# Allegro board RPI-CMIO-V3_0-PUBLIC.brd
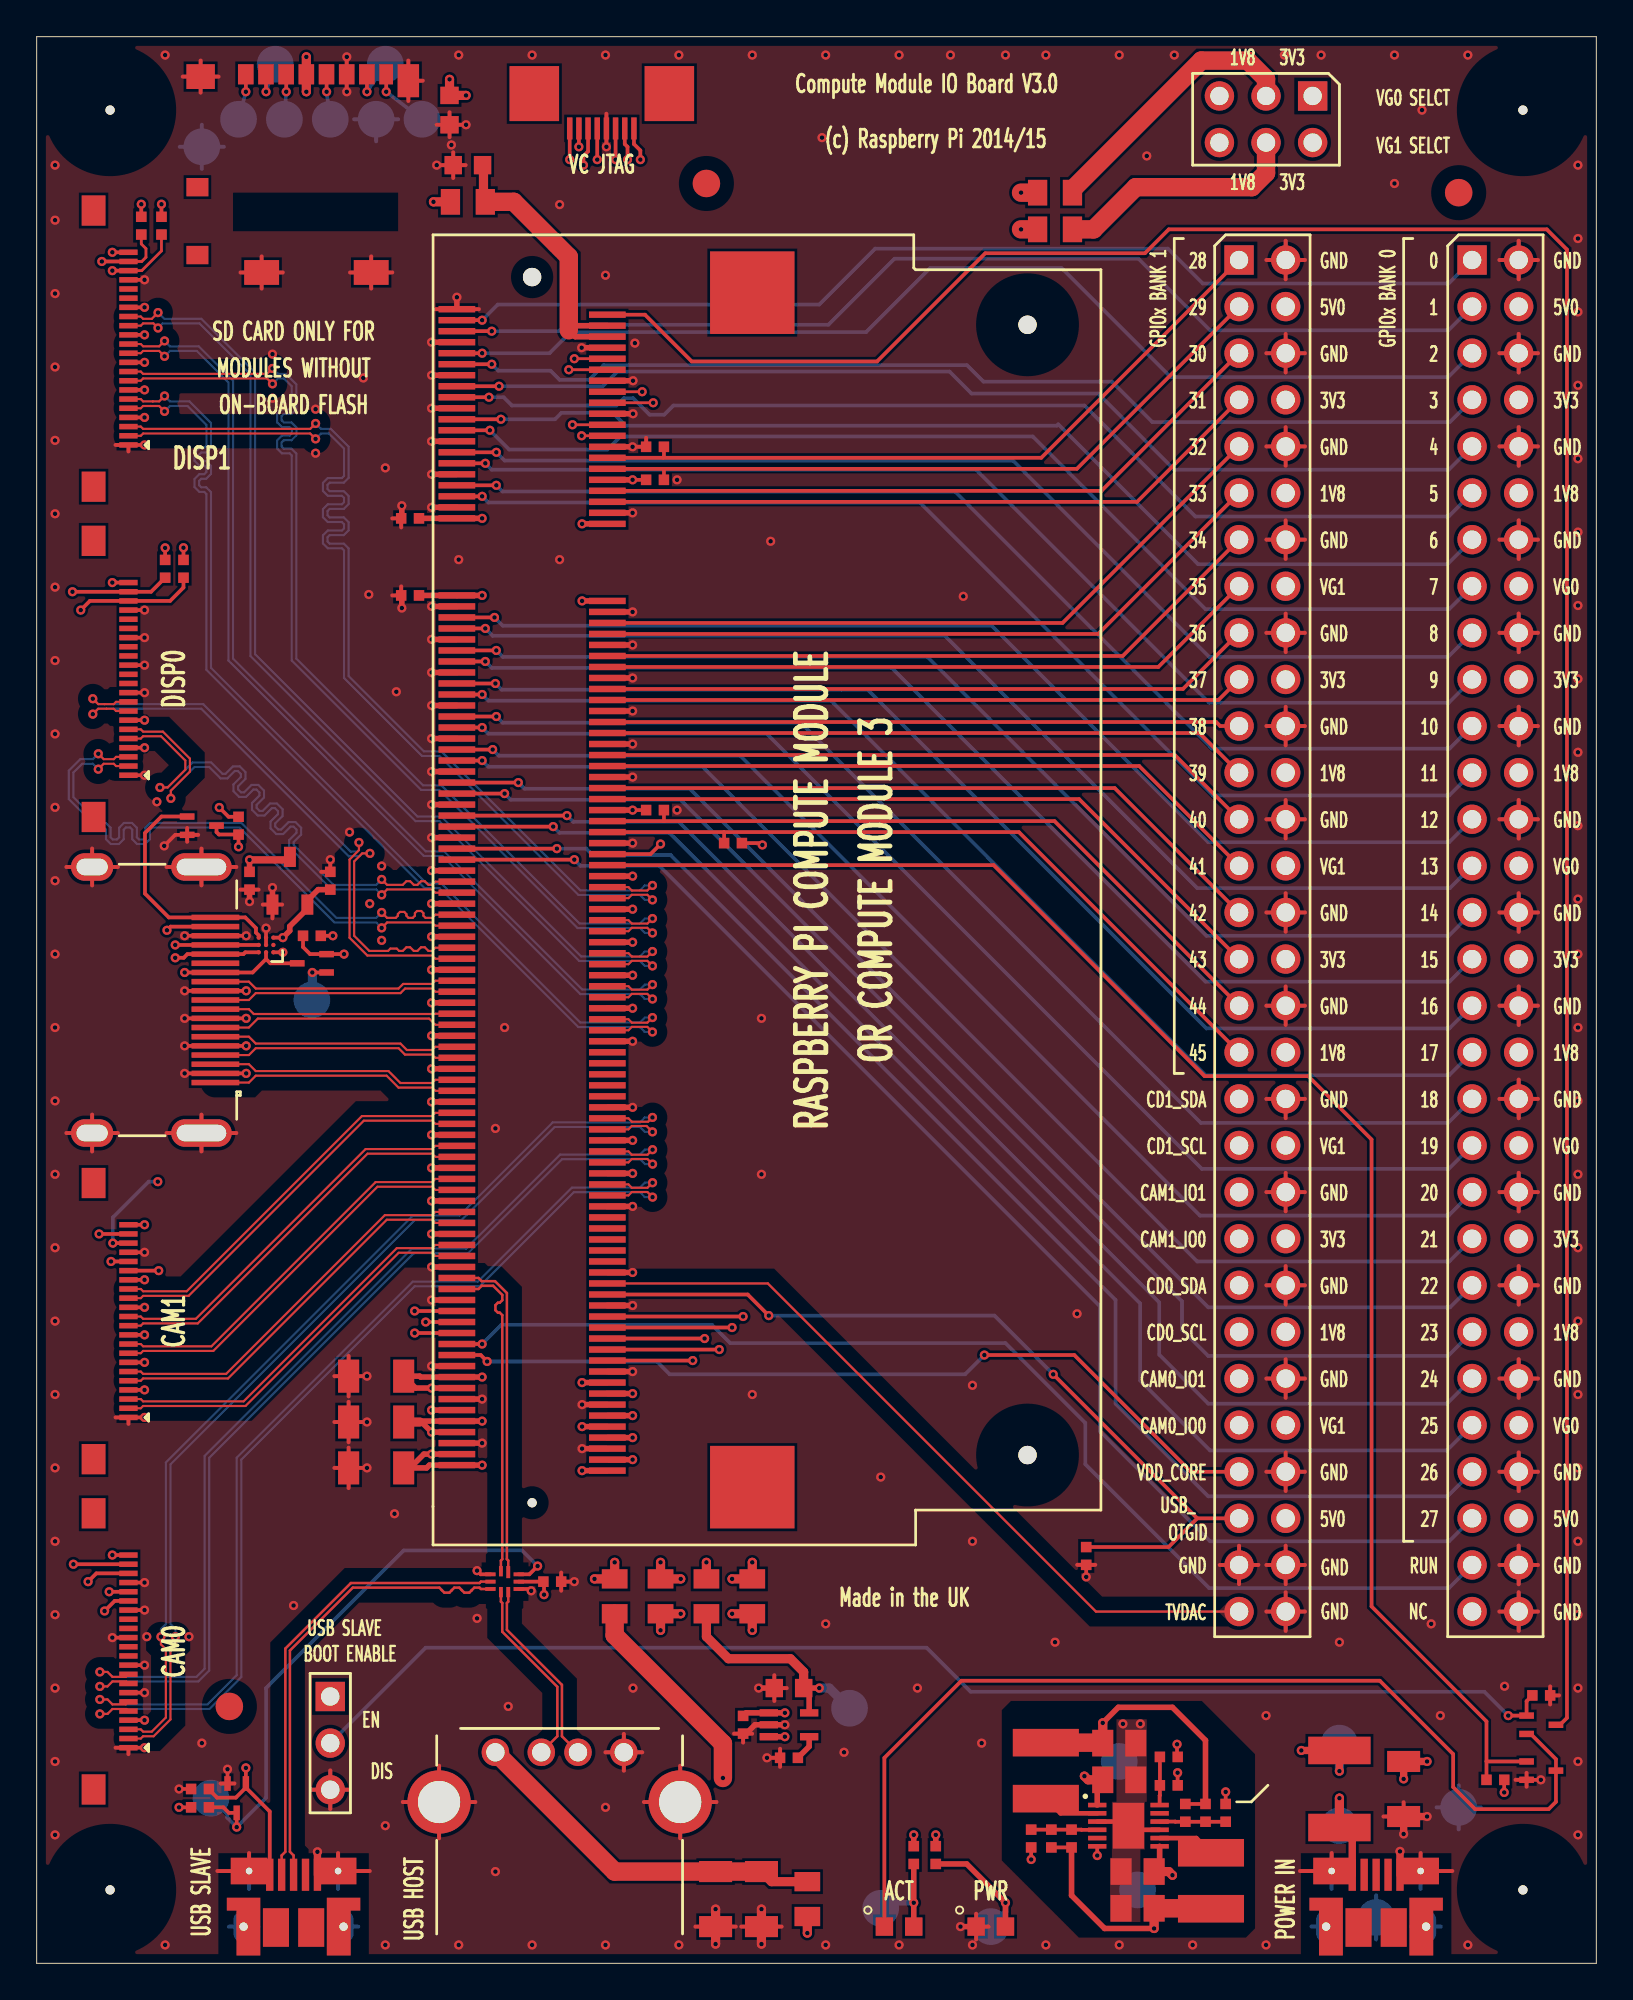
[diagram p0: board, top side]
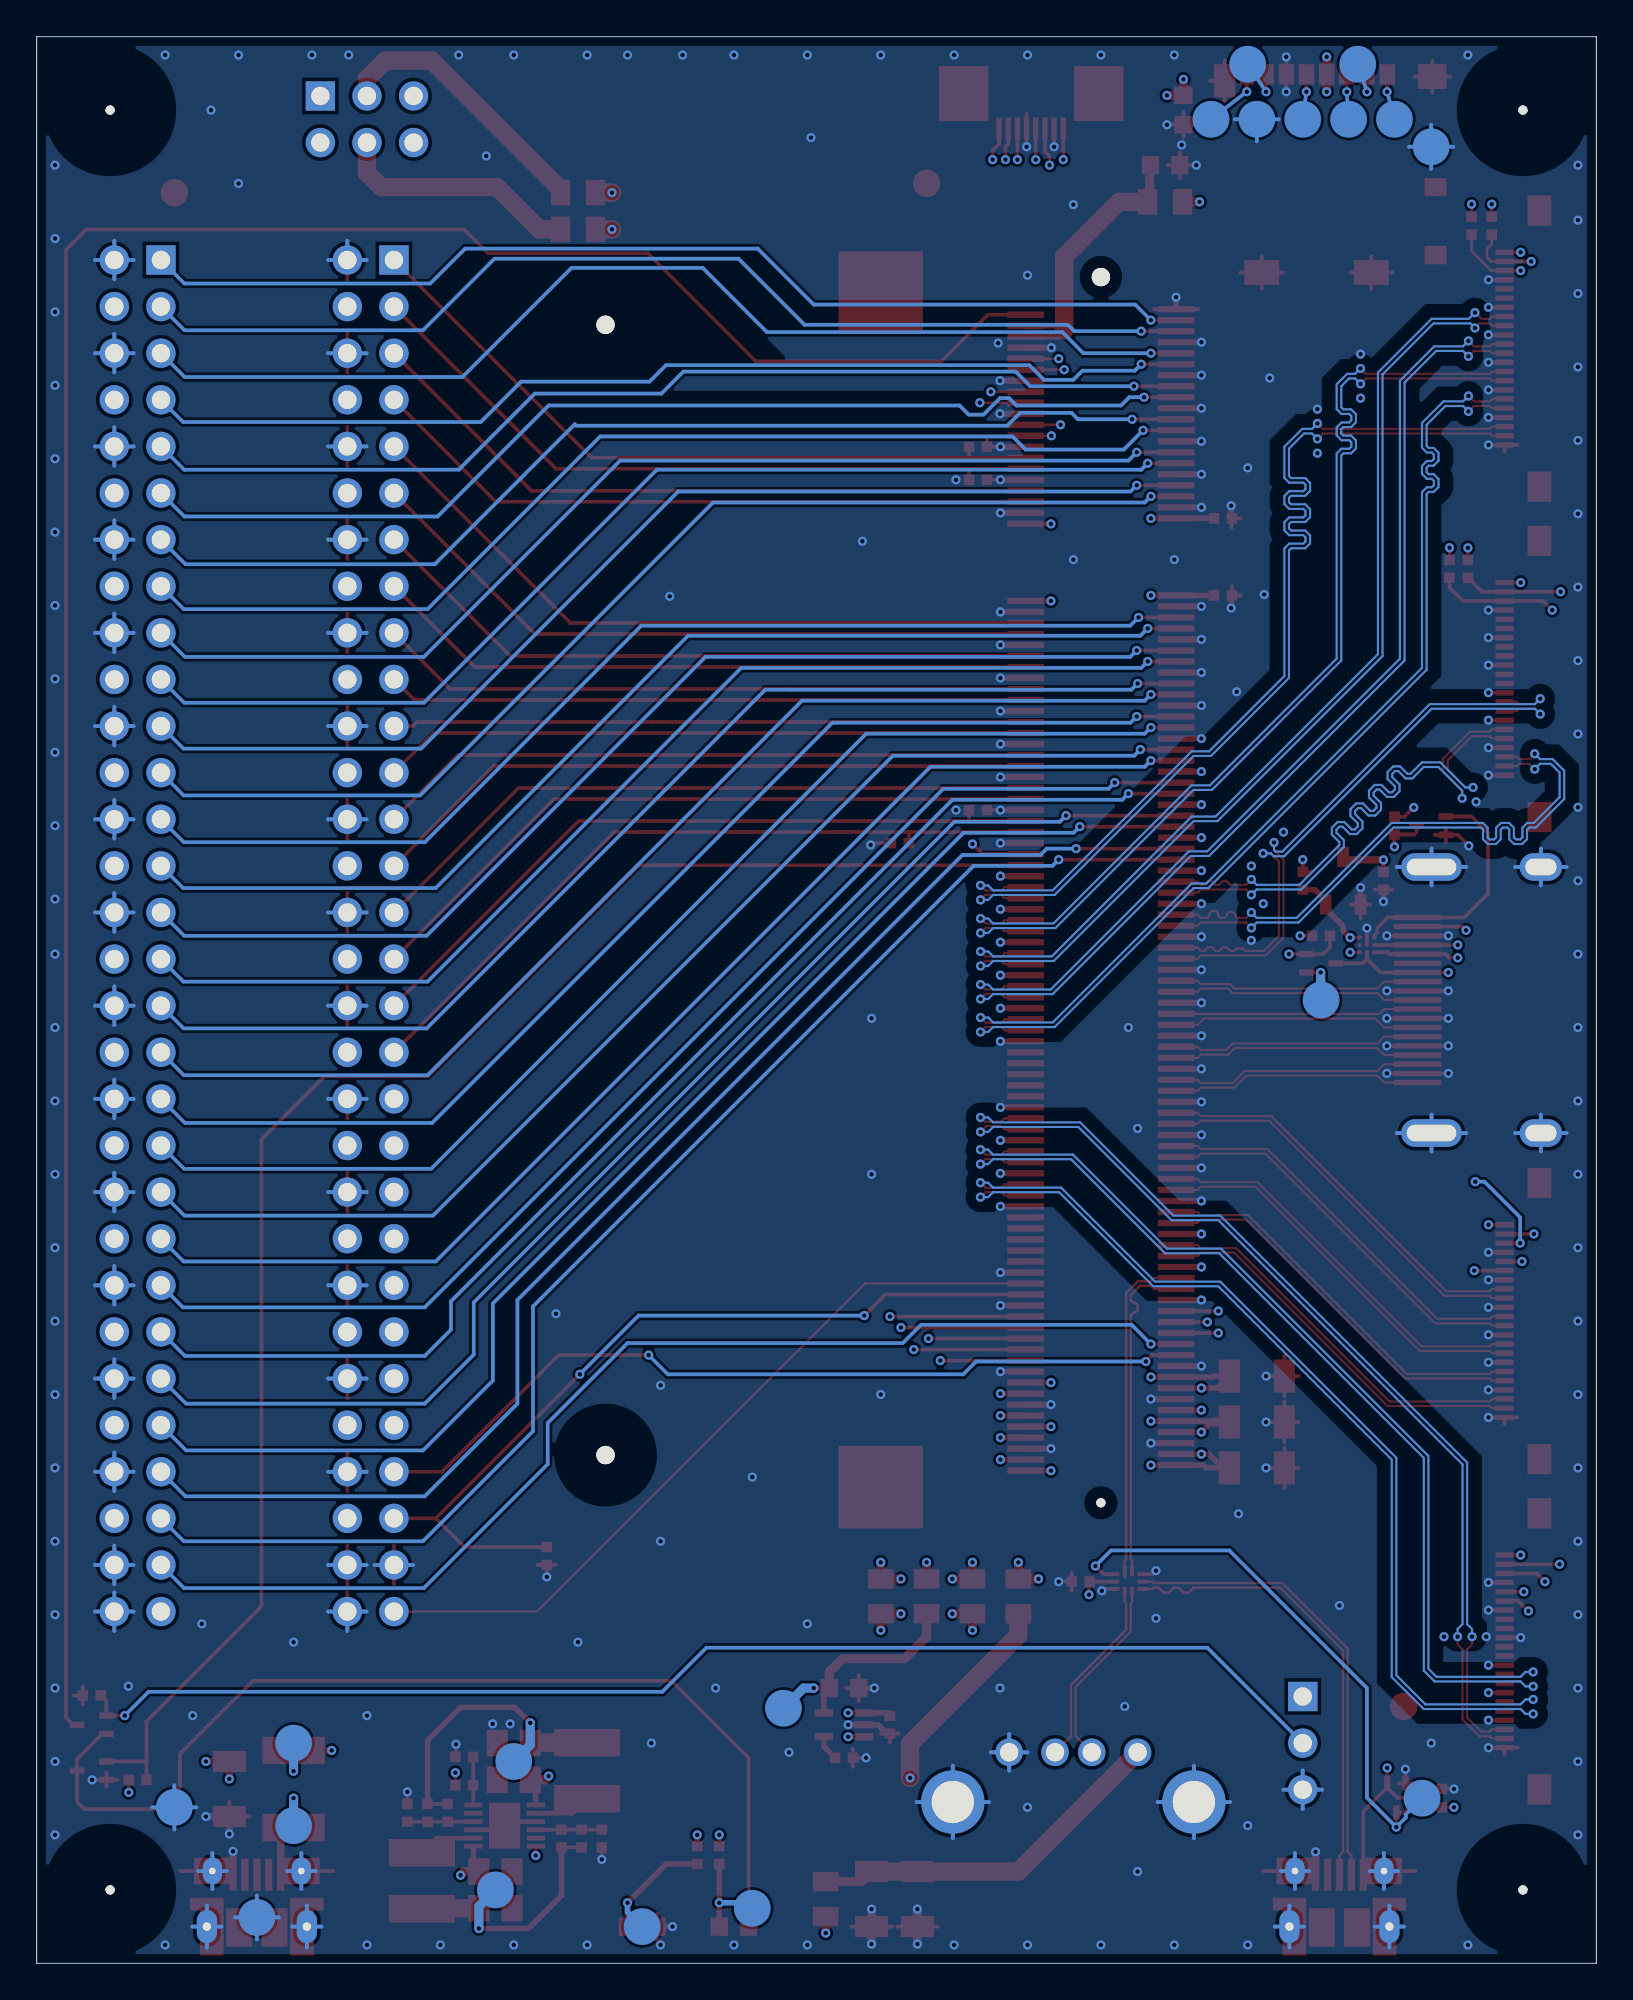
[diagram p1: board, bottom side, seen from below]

Outline 85 x 105 mm; copper layers: TOP, GNDT, PWRT, PWRB, GNDB, BOTTOM. Coordinates in mm from the lower left corner of the outline.
Outline path: 0,105 85,105 85,0 0,0 0,105

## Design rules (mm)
constraint set DEFAULT: min track width 0.115
net group CAM0_CLK: nets CAM0_CN CAM0_CP
net group CAM0_D0: nets CAM0_DN0 CAM0_DP0
net group CAM0_D1: nets CAM0_DN1 CAM0_DP1
net group CAM1_CLK: nets CAM1_CN CAM1_CP
net group CAM1_D0: nets CAM1_DN0 CAM1_DP0
net group CAM1_D1: nets CAM1_DN1 CAM1_DP1
net group CAM1_D2: nets CAM1_DN2 CAM1_DP2
net group CAM1_D3: nets CAM1_DN3 CAM1_DP3
net group DSI0_CLK: nets DSI0_CN DSI0_CP
net group DSI0_D0: nets DSI0_DN0 DSI0_DP0
net group DSI0_D1: nets DSI0_DN1 DSI0_DP1
net group DSI1_CLK: nets DSI1_CN DSI1_CP
net group DSI1_D0: nets DSI1_DN0 DSI1_DP0
net group DSI1_D1: nets DSI1_DN1 DSI1_DP1
net group DSI1_D2: nets DSI1_DN2 DSI1_DP2
net group DSI1_D3: nets DSI1_DN3 DSI1_DP3
net group HDMI_CK: nets HDMI_CK_N HDMI_CK_P
net group HDMI_D0: nets HDMI_D0_N HDMI_D0_P
net group HDMI_D1: nets HDMI_D1_N HDMI_D1_P
net group HDMI_D2: nets HDMI_D2_N HDMI_D2_P
net group USB_D: nets USB_DM USB_DP
net group USBA_D: nets USBA_DM USBA_DP
net group USBB_D: nets USBB_DM USBB_DP

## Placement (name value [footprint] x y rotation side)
C1  47u  [CAPC3216X180N]  18.5 27 180 top
C2  47u  [CAPC3216X180N]  74.5 9.5 270 top
C3  47u  [CAPC3216X180N]  18.5 29.5 180 top
C4  1u  [CAPC1005X55N]  38.5 13 270 top
C5  4.7u  [CAPC1608X90N]  41 15 180 top
C6  100n  [CAPC1005X55N]  61.7 11.25 0 top
C7  10u  [CAPC2012X145N]  60 5 180 top
C8  10u  [CAPC2012X145N]  59 10 0 top
C9  100n  [CAPC1005X55N]  41 11.2 180 top
C10  47u  [CAPC3216X180N]  18.5 32 180 top
C11  10u  [CAPC2012X145N]  60 3 180 top
C12  10u  [CAPC2012X145N]  59 12 0 top
C13  1u  [CAPC1005X55N]  20.35 78.75 180 top
C14  1u  [CAPC1005X55N]  20.35 74.55 180 top
C15  100n  [CAPC1005X55N]  11.6 59 270 top
C16  100n  [CAPC1005X55N]  16 59 90 top
C17  100n  [CAPC1005X55N]  28.1 20.8 180 top
C19  47u  [CAPC3216X180N]  37 3.5 270 top
C20  47u  [CAPC3216X180N]  39.5 3.5 270 top
C21  NF  [CAPC1005X55N]  55.3 6.8 90 top
C22  NF  [CAPC1005X55N]  63.7 8.2 270 top
C23  4.7u  [CAPC1608X90N]  23.5 98 180 top
C24  4.7u  [CAPC1608X90N]  22.5 101 270 top
D1  RED  [LEDC1608X80N]  52 2 0 top
D2  GREEN  [LEDC1608X80N]  47 2 0 top
F1  MF-MSMF200  [BOURNS_MF-MSMF150]  71 9.5 90 top
J1  DDR2 SODIMM  [FCI_10033853_CM]  27 58.5 90 top
J2  10103594-0001LF  [FCI_10103594-0001LF]  73 2 0 top
J3  6W 0.1" PIN HDR  [PINHDR_6W_2P54MM]  67 100.5 180 top
J4  3W 0.1" PIN HDR  [PINHDR_3W_2P54MM]  16 12 270 top
J5  60W 0.1" PIN HDR  [PINHDR_60W_2P54MM]  79.5 56 270 top
J6  60W 0.1" PIN HDR  [PINHDR_60W_2P54MM]  66.8 56 270 top
J7  68710814522  [WE_68710814522]  30.8 100 180 top
J9  54548-2271  [MOLEX_54548-2271]  5 17 270 top
J10  54548-2271  [MOLEX_54548-2271]  5 70 270 top
J11  54548-2271  [MOLEX_54548-2271]  5 35 270 top
J12  54548-2271  [MOLEX_54548-2271]  5 88 270 top
J13  47151-1051  [MOLEX_47151-1051]  6 52.5 270 top
J14  61400416021  [WURTH_61400416021]  28.5 11.5 90 top
J15  10103594-0001LF  [FCI_10103594-0001LF]  14 2 0 top
J16  1040310811  [MOLEX_1040310811]  14.5 98 180 top
L1  4.7u  [BOURNS_SRN4018]  64 4.5 270 top
L2  4.7u  [BOURNS_SRN4018]  55 10.5 90 top
NOREF  -  []  0 105 0 top
NOREF#2  -  []  110 65 0 top
NOREF#3  -  []  85 0 90 top
NOREF#4  -  [unnamed#2]  77.5 96.5 0 top
NOREF#5  -  [unnamed#2]  10.5 14 0 top
NOREF#6  -  []  110 0 0 top
NOREF#7  -  []  110 34 0 top
NOREF#8  -  [unnamed#2]  4 4 0 top
NOREF#9  -  [unnamed#2]  4 101 0 top
NOREF#10  -  [unnamed#2]  81 101 0 top
NOREF#11  -  [unnamed#2]  81 4 0 top
NOREF#12  -  []  0 129 0 top
NOREF#13  -  []  0 166 0 top
NOREF#14  -  [unnamed#2]  36.5 97 0 top
PP1  PP_SMT_ROUND_2MM  [PP_SMT_R2MM]  71 7.5 180 bottom
PP2  PP_SMT_ROUND_2MM  [PP_SMT_R2MM]  60 4 180 bottom
PP3  PP_SMT_ROUND_2MM  [PP_SMT_R2MM]  71 12 180 bottom
PP4  PP_SMT_ROUND_2MM  [PP_SMT_R2MM]  44.3 13.9 180 bottom
PP5  PP_SMT_ROUND_2MM  [PP_SMT_R2MM]  77.5 8.5 180 bottom
PP6  PP_SMT_ROUND_2MM  [PP_SMT_R2MM]  59 11 180 bottom
PP7  PP_SMT_ROUND_2MM  [PP_SMT_R2MM]  52 2 180 bottom
PP8  PP_SMT_ROUND_2MM  [PP_SMT_R2MM]  73 2.5 180 bottom
PP9  PP_SMT_ROUND_2MM  [PP_SMT_R2MM]  46 3 180 bottom
PP10  PP_SMT_ROUND_2MM  [PP_SMT_R2MM]  15 52.5 180 bottom
PP11  PP_SMT_ROUND_2MM  [PP_SMT_R2MM]  9.5 9 180 bottom
PP12  PP_SMT_ROUND_2MM  [PP_SMT_R2MM]  11 100.5 180 bottom
PP13  PP_SMT_ROUND_2MM  [PP_SMT_R2MM]  13 103.5 180 bottom
PP14  PP_SMT_ROUND_2MM  [PP_SMT_R2MM]  13.5 100.5 180 bottom
PP15  PP_SMT_ROUND_2MM  [PP_SMT_R2MM]  16 100.5 180 bottom
PP16  PP_SMT_ROUND_2MM  [PP_SMT_R2MM]  19 103.5 180 bottom
PP17  PP_SMT_ROUND_2MM  [PP_SMT_R2MM]  21 100.5 180 bottom
PP18  PP_SMT_ROUND_2MM  [PP_SMT_R2MM]  18.5 100.5 180 bottom
PP19  PP_SMT_ROUND_2MM  [PP_SMT_R2MM]  9 99 180 bottom
Q1  DMG1012T  [SOT50P160X90-3N]  82 13 0 top
Q2  DMG1012T  [SOT50P160X90-3N]  82 10.5 0 top
Q3  DMG1012T  [SOT50P160X90-3N]  15 54.5 180 top
Q4  DMG1012T  [SOT50P160X90-3N]  9 62 0 top
Q5  DMG1012T  [SOT50P160X90-3N]  10.9 9 270 top
R1  0R  [RESC2012X65N]  31.5 20 90 top
R2  100K  [RESC1005X40N]  61.7 9.7 180 top
R3  470R  [RESC1005X40N]  49 5.9 270 top
R4  0R  [RESC2012X65N]  34 20 90 top
R5  0R  [RESC2012X65N]  39 20 90 top
R6  0R  [RESC2012X65N]  36.5 20 90 top
R7  0R  [RESC2012X65N]  55.5 96.5 0 top
R8  0R  [RESC2012X65N]  55.5 94.5 0 top
R9  470R  [RESC1005X40N]  47.8 5.9 270 top
R10  100K  [RESC1005X40N]  79.5 10 180 top
R12  1K  [RESC1005X40N]  57.2 22.2 90 top
R13  1.8K  [RESC1005X40N]  8 76 270 top
R14  1.8K  [RESC1005X40N]  7 76 270 top
R15  NF  [RESC1005X40N]  15 56 0 top
R16  1.8K  [RESC1005X40N]  6.8 94.7 270 top
R17  1.8K  [RESC1005X40N]  5.7 94.7 270 top
R18  100K  [RESC1005X40N]  11 62 270 top
R19  0R  [RESC2012X65N]  42 3.5 90 top
R20  47K  [RESC1005X40N]  8.9 8.5 0 top
R21  47K  [RESC1005X40N]  8.9 9.5 180 top
R22  0R  [RESC1005X40N]  56.4 6.8 90 top
R23  0R  [RESC1005X40N]  62.6 8.2 270 top
R24  NF  [RESC1005X40N]  64.8 8.2 90 top
R25  NF  [RESC1005X40N]  54.2 6.8 270 top
R26  100K  [RESC1005X40N]  33.7 80.85 180 top
R27  100K  [RESC1005X40N]  33.7 82.65 180 top
R28  100K  [RESC1005X40N]  37.95 61.05 0 top
R29  100K  [RESC1005X40N]  33.7 62.85 180 top
R30  47K  [RESC1005X40N]  82 14.6 0 top
R31  0R  [RESC2012X65N]  23.5 96 180 top
U1  PAM2306AYPKE  [DIODES_PAM2306]  59.5 7.5 0 top
U2  AP7115-25SEG  [SOT65P210X100-5N]  41 13 0 top
U3  AP2331W  [SOT95P280X135-3N]  13.8 59 90 top
U4  ESD5384  [ONSEMI_ESD5384]  12.5 55.5 180 top
U5  FSUSB42UMX  [FAIRCHILD_FSUSB42UMX]  25.5 20.8 270 top

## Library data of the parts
C1-C3 C10 C19 C20 = CAP_3216_6.3V_47u
C4 C13 C14 = CAP_1005_6.3V_1u
C5 C23 C24 = CAP_1608_6.3V_4.7u
C6 C9 C15-C17 = CAP_1005_6.3V_100n
C7 C8 C11 C12 = CAP_2012_6.3V_10u
C21 C22 = CAP_1005_NF
D1 = LED_1608_RED
D2 = LED_1608_GREEN
F1 = FUSE_POLY_2.0A_6V
J1 = CON_200W_DDR2SODIMM_CM
J2 J15 = CON_uUSB_B
J3 = CON_6W_PINHDR
J4 = CON_3W_PINHDR
J5 J6 = CON_60W_PINHDR
J7 = CON_FFC_8W
J9-J12 = CON_22W_FFC_54548-2271
J13 = CON_HDMI_RA
J14 = CON_USBA_RA_PTH
J16 = CON_uSD_1040310811
L1 L2 = IND_4u7_SRN4018-4R7M
PP1-PP19 = PP_SMT_ROUND_2MM
Q1-Q5 = MOSFET_N_DMG1012T
R1 R4-R8 R19 R31 = RES_2012_0R
R2 R10 R18 R26-R29 = RES_1005_100K
R3 R9 = RES_1005_470R
R12 = RES_1005_1K
R13 R14 R16 R17 = RES_1005_1.8K
R15 = RES_1005_27K
R20 R21 R30 = RES_1005_47K
R22 R23 = RES_1005_0R
R24 R25 = RES_1005_NF
U1 = IC_SMPS_DUAL_1A_3V3_1V8
U2 = IC_AP7115-25SEG
U3 = IC_AP2331W
U4 = IC_ESD5384
U5 = IC_MUX2-1_USB

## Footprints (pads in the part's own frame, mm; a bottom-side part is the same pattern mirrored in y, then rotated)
BOURNS_MF-MSMF150
  rect 1.5x3.4 smd: 1(-2.1,0) 2(2.1,0)
BOURNS_SRN4018
  rect 1.5x3.6 smd: 1(-1.525,0) 2(1.525,0)
CAPC1005X55N
  rect 0.57x0.58 smd: 1(-0.485,0) 2(0.485,0)
CAPC1608X90N
  rect 0.95x1 smd: 1(-0.8,0) 2(0.8,0)
CAPC2012X145N
  rect 1.15x1.45 smd: 1(-0.9,0) 2(0.9,0)
CAPC3216X180N
  rect 1.15x1.8 smd: 1(-1.5,0) 2(1.5,0)
DIODES_PAM2306
  rect 1x0.25 smd: 1(-1.7,1.125) 2(-1.7,0.675) 3(-1.7,0.225) 4(-1.7,-0.225) 5(-1.7,-0.675) 6(-1.7,-1.125) 7(1.7,-1.125) 8(1.7,-0.675) 9(1.7,-0.225) 10(1.7,0.225) 11(1.7,0.675) 12(1.7,1.125)
  rect 1.7x2.5 smd: 13(0,0)
FAIRCHILD_FSUSB42UMX
  rect 0.66x0.21 smd: 1(-0.52,0.2)
  rect 0.56x0.21 smd: 2(-0.57,-0.2) 6(0.57,-0.2) 7(0.57,0.2)
  rect 0.21x0.56 smd: 3(-0.4,-0.77) 4(0,-0.77) 5(0.4,-0.77) 8(0.4,0.77) 9(0,0.77) 10(-0.4,0.77)
FCI_10033853_CM
  round 0.5 hole 1.1 unplated: (-33.4,0)
  rect 4.5x4.6 smd: (-32.55,-12) (32.55,-12)
  round 1 hole 2.4 unplated: (-30.8,-27) (30.8,-27)
  round 1 hole 1.6 unplated: (33.4,0)
  rect 0.35x2 smd: 1(31.65,4.1) 2(31.35,-4.1) 3(31.05,4.1) 4(30.75,-4.1) 5(30.45,4.1) 6(30.15,-4.1) 7(29.85,4.1) 8(29.55,-4.1) 9(29.25,4.1) 10(28.95,-4.1) 11(28.65,4.1) 12(28.35,-4.1) 13(28.05,4.1) 14(27.75,-4.1) 15(27.45,4.1) 16(27.15,-4.1) 17(26.85,4.1) 18(26.55,-4.1) 19(26.25,4.1) 20(25.95,-4.1) 21(25.65,4.1) 22(25.35,-4.1) 23(25.05,4.1) 24(24.75,-4.1) 25(24.45,4.1) 26(24.15,-4.1) 27(23.85,4.1) 28(23.55,-4.1) 29(23.25,4.1) 30(22.95,-4.1) 31(22.65,4.1) 32(22.35,-4.1) 33(22.05,4.1) 34(21.75,-4.1) 35(21.45,4.1) 36(21.15,-4.1) 37(20.85,4.1) 38(20.55,-4.1) 39(20.25,4.1) 40(19.95,-4.1) 41(16.05,4.1) 42(15.75,-4.1) 43(15.45,4.1) 44(15.15,-4.1) 45(14.85,4.1) 46(14.55,-4.1) 47(14.25,4.1) 48(13.95,-4.1) 49(13.65,4.1) 50(13.35,-4.1) 51(13.05,4.1) 52(12.75,-4.1) 53(12.45,4.1) 54(12.15,-4.1) 55(11.85,4.1) 56(11.55,-4.1) 57(11.25,4.1) 58(10.95,-4.1) 59(10.65,4.1) 60(10.35,-4.1) 61(10.05,4.1) 62(9.75,-4.1) 63(9.45,4.1) 64(9.15,-4.1) 65(8.85,4.1) 66(8.55,-4.1) 67(8.25,4.1) 68(7.95,-4.1) 69(7.65,4.1) 70(7.35,-4.1) 71(7.05,4.1) 72(6.75,-4.1) 73(6.45,4.1) 74(6.15,-4.1) 75(5.85,4.1) 76(5.55,-4.1) 77(5.25,4.1) 78(4.95,-4.1) 79(4.65,4.1) 80(4.35,-4.1) 81(4.05,4.1) 82(3.75,-4.1) 83(3.45,4.1) 84(3.15,-4.1) 85(2.85,4.1) 86(2.55,-4.1) 87(2.25,4.1) 88(1.95,-4.1) 89(1.65,4.1) 90(1.35,-4.1) 91(1.05,4.1) 92(0.75,-4.1) 93(0.45,4.1) 94(0.15,-4.1) 95(-0.15,4.1) 96(-0.45,-4.1) 97(-0.75,4.1) 98(-1.05,-4.1) 99(-1.35,4.1) 100(-1.65,-4.1) 101(-1.95,4.1) 102(-2.25,-4.1) 103(-2.55,4.1) 104(-2.85,-4.1) 105(-3.15,4.1) 106(-3.45,-4.1) 107(-3.75,4.1) 108(-4.05,-4.1) 109(-4.35,4.1) 110(-4.65,-4.1) 111(-4.95,4.1) 112(-5.25,-4.1) 113(-5.55,4.1) 114(-5.85,-4.1) 115(-6.15,4.1) 116(-6.45,-4.1) 117(-6.75,4.1) 118(-7.05,-4.1) 119(-7.35,4.1) 120(-7.65,-4.1) 121(-7.95,4.1) 122(-8.25,-4.1) 123(-8.55,4.1) 124(-8.85,-4.1) 125(-9.15,4.1) 126(-9.45,-4.1) 127(-9.75,4.1) 128(-10.05,-4.1) 129(-10.35,4.1) 130(-10.65,-4.1) 131(-10.95,4.1) 132(-11.25,-4.1) 133(-11.55,4.1) 134(-11.85,-4.1) 135(-12.15,4.1) 136(-12.45,-4.1) 137(-12.75,4.1) 138(-13.05,-4.1) 139(-13.35,4.1) 140(-13.65,-4.1) 141(-13.95,4.1) 142(-14.25,-4.1) 143(-14.55,4.1) 144(-14.85,-4.1) 145(-15.15,4.1) 146(-15.45,-4.1) 147(-15.75,4.1) 148(-16.05,-4.1) 149(-16.35,4.1) 150(-16.65,-4.1) 151(-16.95,4.1) 152(-17.25,-4.1) 153(-17.55,4.1) 154(-17.85,-4.1) 155(-18.15,4.1) 156(-18.45,-4.1) 157(-18.75,4.1) 158(-19.05,-4.1) 159(-19.35,4.1) 160(-19.65,-4.1) 161(-19.95,4.1) 162(-20.25,-4.1) 163(-20.55,4.1) 164(-20.85,-4.1) 165(-21.15,4.1) 166(-21.45,-4.1) 167(-21.75,4.1) 168(-22.05,-4.1) 169(-22.35,4.1) 170(-22.65,-4.1) 171(-22.95,4.1) 172(-23.25,-4.1) 173(-23.55,4.1) 174(-23.85,-4.1) 175(-24.15,4.1) 176(-24.45,-4.1) 177(-24.75,4.1) 178(-25.05,-4.1) 179(-25.35,4.1) 180(-25.65,-4.1) 181(-25.95,4.1) 182(-26.25,-4.1) 183(-26.55,4.1) 184(-26.85,-4.1) 185(-27.15,4.1) 186(-27.45,-4.1) 187(-27.75,4.1) 188(-28.05,-4.1) 189(-28.35,4.1) 190(-28.65,-4.1) 191(-28.95,4.1) 192(-29.25,-4.1) 193(-29.55,4.1) 194(-29.85,-4.1) 195(-30.15,4.1) 196(-30.45,-4.1) 197(-30.75,4.1) 198(-31.05,-4.1) 199(-31.35,4.1) 200(-31.65,-4.1)
FCI_10103594-0001LF
  rect 1.42x2.1 smd: (-0.96,-0.05) (0.96,-0.05)
  rect 0.4x1.75 smd: 1(-1.3,2.825) 2(-0.65,2.825) 3(0,2.825) 4(0.65,2.825) 5(1.3,2.825)
  custom 0.362x0.362 hole 1.05x0.65: 6(-2.425,3.03) 8(2.425,3.03)
  custom 0.456x0.456 hole 0.7x1.4: 7(-2.725,0) 9(2.725,0)
LEDC1608X80N
  rect 0.95x1 smd: 1(-0.8,0) 2(0.8,0)
MOLEX_47151-1051
  rect 0.3x2.6 smd: 1(4.5,3.74) 2(4,3.74) 3(3.5,3.74) 4(3,3.74) 5(2.5,3.74) 6(2,3.74) 7(1.5,3.74) 8(1,3.74) 9(0.5,3.74) 10(0,3.74) 11(-0.5,3.74) 12(-1,3.74) 13(-1.5,3.74) 14(-2,3.74) 15(-2.5,3.74) 16(-3,3.74) 17(-3.5,3.74) 18(-4,3.74) 19(-4.5,3.74)
  oval 1.5x3.3 hole 0.9x2.7: 20(7.25,2.98) 22(-7.25,2.98)
  oval 1.5x2.3 hole 0.9x1.7: 21(7.25,-2.98) 23(-7.25,-2.98)
MOLEX_54548-2271
  rect 1.65x1.3 smd: (-7.525,-1.9) (7.525,-1.9)
  rect 0.3x1 smd: 1(5.25,0) 2(4.75,0) 3(4.25,0) 4(3.75,0) 5(3.25,0) 6(2.75,0) 7(2.25,0) 8(1.75,0) 9(1.25,0) 10(0.75,0) 11(0.25,0) 12(-0.25,0) 13(-0.75,0) 14(-1.25,0) 15(-1.75,0) 16(-2.25,0) 17(-2.75,0) 18(-3.25,0) 19(-3.75,0) 20(-4.25,0) 21(-4.75,0) 22(-5.25,0)
MOLEX_1040310811
  rect 0.85x1.1 smd: 1(3.105,-4.95) 2(2.005,-4.95) 3(0.905,-4.95) 4(-0.195,-4.95) 5(-1.295,-4.95) 6(-2.395,-4.95) 7(-3.495,-4.95)
  rect 0.75x1.1 smd: 8(-4.545,-4.95)
  rect 1.2x1 smd: 9(5.74,1.2) 10(5.74,4.9)
  rect 1.17x1.8 smd: 11(-5.755,-4.6)
  rect 1.55x1.35 smd: 12(5.565,-4.825)
  rect 1.9x1.35 smd: 13(2.24,5.85) 14(-3.73,5.85)
ONSEMI_ESD5384
  round 0.235 smd: A1(-0.4,0.4) A2(0,0.4) A3(0.4,0.4) B1(-0.4,0) B2(0,0) B3(0.4,0) C1(-0.4,-0.4) C2(0,-0.4) C3(0.4,-0.4)
PINHDR_3W_2P54MM
  rect 1.6x1.6 hole 1: 1(-2.54,0)
  round 1.6 hole 1: 2(0,0) 3(2.54,0)
PINHDR_6W_2P54MM
  rect 1.6x1.6 hole 1: 1(-2.54,-1.27)
  round 1.6 hole 1: 2(-2.54,1.27) 3(0,-1.27) 4(0,1.27) 5(2.54,-1.27) 6(2.54,1.27)
PINHDR_60W_2P54MM
  rect 1.6x1.6 hole 1: 1(-36.83,-1.27)
  round 1.6 hole 1: 2(-36.83,1.27) 3(-34.29,-1.27) 4(-34.29,1.27) 5(-31.75,-1.27) 6(-31.75,1.27) 7(-29.21,-1.27) 8(-29.21,1.27) 9(-26.67,-1.27) 10(-26.67,1.27) 11(-24.13,-1.27) 12(-24.13,1.27) 13(-21.59,-1.27) 14(-21.59,1.27) 15(-19.05,-1.27) 16(-19.05,1.27) 17(-16.51,-1.27) 18(-16.51,1.27) 19(-13.97,-1.27) 20(-13.97,1.27) 21(-11.43,-1.27) 22(-11.43,1.27) 23(-8.89,-1.27) 24(-8.89,1.27) 25(-6.35,-1.27) 26(-6.35,1.27) 27(-3.81,-1.27) 28(-3.81,1.27) 29(-1.27,-1.27) 30(-1.27,1.27) 31(1.27,-1.27) 32(1.27,1.27) 33(3.81,-1.27) 34(3.81,1.27) 35(6.35,-1.27) 36(6.35,1.27) 37(8.89,-1.27) 38(8.89,1.27) 39(11.43,-1.27) 40(11.43,1.27) 41(13.97,-1.27) 42(13.97,1.27) 43(16.51,-1.27) 44(16.51,1.27) 45(19.05,-1.27) 46(19.05,1.27) 47(21.59,-1.27) 48(21.59,1.27) 49(24.13,-1.27) 50(24.13,1.27) 51(26.67,-1.27) 52(26.67,1.27) 53(29.21,-1.27) 54(29.21,1.27) 55(31.75,-1.27) 56(31.75,1.27) 57(34.29,-1.27) 58(34.29,1.27) 59(36.83,-1.27) 60(36.83,1.27)
PP_SMT_R2MM
  round 2 smd: 1(0,0)
RESC1005X40N
  rect 0.57x0.58 smd: 1(-0.485,0) 2(0.485,0)
RESC2012X65N
  rect 1.05x1.4 smd: 1(-0.95,0) 2(0.95,0)
SOT50P160X90-3N
  rect 0.8x0.35 smd: 1(-0.8,0.5) 2(-0.8,-0.5) 3(0.8,0)
SOT65P210X100-5N
  rect 1x0.4 smd: 1(-1.1,0.65) 2(-1.1,0) 3(-1.1,-0.65) 4(1.1,-0.65) 5(1.1,0.65)
SOT95P280X135-3N
  rect 1.1x0.65 smd: 1(-1.3,0.95) 2(-1.3,-0.95) 3(1.3,0)
unnamed#2
  round 1.5 smd: (0,0)
WE_68710814522
  rect 2.7x3 smd: (-3.68,-1.9) (3.68,-1.9)
  rect 0.3x1.2 smd: 1(-1.75,0) 2(-1.25,0) 3(-0.75,0) 4(-0.25,0) 5(0.25,0) 6(0.75,0) 7(1.25,0) 8(1.75,0)
WURTH_61400416021
  round 1.5 hole 1: 1(0,3.5) 2(0,1) 3(0,-1) 4(0,-3.5)
  round 3.45 hole 2.3: 5(-2.71,6.57) 6(-2.71,-6.57)

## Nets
1V8: C12.1 C22.1 J3.5 J3.6(P6) J5.12 J5.24 J5.36 J5.48 J6.12 J6.24 J6.36 J6.48 L2.2 PP6.1 R5.1 R10.1 R18.1 R23.1
3V3: C4.1 C11.1 C17.2 C21.1 C24.1 J3.1 J3.2 J5.8 J5.20 J5.32 J5.44 J6.8 J6.20 J6.32 J6.44 J9.22 J10.22 J11.22 J12.22 J16.4 L1.2 PP2.1 R3.1 R4.1 R9.1 R13.1 R14.1 R15.2 R16.1 R17.1 R20.1 R22.1 R31.2 U2.1 U2.3 U5.9(VCC)
5V: C2.1 C7.1 C8.1 C15.1 F1.2(P2) J5.4 J5.56 J6.4 J6.56 PP3.1 R1.1 R2.1 R19.1 U1.1(VIN2) U1.6 U1.7 U3.3
GND: C1.2 C2.2 C3.2 C4.2 C5.2 C6.2 C7.2 C8.2 C9.2 C10.2 C11.2 C12.2 C13.2 C14.2 C15.2 C16.2 C17.1 C19.2 C20.2 C23.2 C24.2 D1.1(CATHODE) J1.1 J1.7 J1.8 J1.13 J1.14 J1.19 J1.20 J1.25 J1.26 J1.31 J1.32 J1.37 J1.38 J1.43 J1.44 J1.49 J1.50 J1.55 J1.56 J1.61 J1.62 J1.67 J1.68 J1.73 J1.74 J1.79 J1.80 J1.85 J1.86 J1.91 J1.92 J1.97 J1.98 J1.103 J1.104 J1.109 J1.110 J1.115 J1.116 J1.121 J1.122 J1.127 J1.133 J1.134 J1.139 J1.140 J1.145 J1.146 J1.151 J1.152 J1.157 J1.163 J1.164 J1.169 J1.170 J1.181 J1.182 J1.187 J1.188 J1.195 J1.196 J2.5 J2.6 J2.7 J2.8 J2.9(SH4) J4.3(P3) J5.2 J5.6 J5.10 J5.14 J5.18 J5.22 J5.26 J5.30 J5.34 J5.38 J5.42 J5.46 J5.50 J5.54 J5.58 J5.60 J6.2 J6.6 J6.10 J6.14 J6.18 J6.22 J6.26 J6.30 J6.34 J6.38 J6.42 J6.46 J6.50 J6.54 J6.57 J6.58 J6.60 J7.4 J7.7 J9.1 J9.4 J9.7 J9.10 J9.13 J9.16 J9.19 J10.1 J10.4 J10.7 J10.10 J10.13 J10.16 J10.19 J11.1 J11.4 J11.7 J11.10 J11.13 J11.16 J11.19 J12.1 J12.4 J12.7 J12.10 J12.13 J12.16 J12.19 J13.2 J13.5 J13.8 J13.11 J13.17 J13.20 J13.21 J13.22 J13.23(SH4) J14.4 J14.5 J14.6(P6) J15.5 J15.6 J15.7 J15.8 J15.9(SH4) J16.6(VSS) J16.11 J16.12 J16.13 J16.14 PP5.1 PP8.1 PP18.1 PP19.1 Q2.2(S) Q4.2(S) Q5.2(S) R12.1 R21.2 R24.2 R25.2 R26.2 R27.2 R28.2 R29.2 R30.2 U1.3 U1.9 U1.13 U2.2 U3.1 U4.B2 U4.C2 U5.3 U5.8
VBUSA: C19.1 C20.1 J14.1 R19.2
VBUSB: J4.1 J15.1 Q5.1 R21.1
VDD_CORE: J1.179 J6.53
CAM0_CN: J1.144 J9.8
CAM0_CP: J1.142 J9.9(P9)
CAM0_DN0: J1.138 J9.2
CAM0_DN1: J1.150 J9.5
CAM0_DP0: J1.136 J9.3
CAM0_DP1: J1.148 J9.6
CAM0_IO0: J6.51 J9.17
CAM0_IO1: J6.49 J9.18
CAM1_CN: J1.149 J11.8
CAM1_CP: J1.147 J11.9(P9)
CAM1_DN0: J1.161 J11.2
CAM1_DN1: J1.155 J11.5
CAM1_DN2: J1.143 J11.11
CAM1_DN3: J1.137 J11.14
CAM1_DP0: J1.159 J11.3
CAM1_DP1: J1.153 J11.6
CAM1_DP2: J1.141 J11.12
CAM1_DP3: J1.135 J11.15
CAM1_IO0: J6.43 J11.17
CAM1_IO1: J6.41 J11.18
CD0_SCL: J6.47 J9.20 J10.20 R13.2
CD0_SDA: J6.45 J9.21 J10.21 R14.2
CD1_SCL: J6.39 J11.20 J12.20 R16.2
CD1_SDA: J6.37 J11.21 J12.21 R17.2
CEC: J13.13 Q3.3 U4.A2
CM_1V8: C10.1 J1.183 J1.184 J1.185 J1.186 R5.2
CM_3V3: C3.1 J1.191 J1.192 J1.193 J1.194 R4.2
CM_VBAT: C1.1 J1.197 J1.198 J1.199 J1.200 R1.2
CM_VDAC: J1.189 J1.190 R6.2
DAC_2V5: C5.1 PP4.1 R6.1 U2.5(VOUT)
DSI0_CN: J1.105 J10.8
DSI0_CP: J1.107 J10.9(P9)
DSI0_DN0: J1.99 J10.2
DSI0_DN1: J1.93 J10.5
DSI0_DP0: J1.101 J10.3
DSI0_DP1: J1.95 J10.6
DSI1_CN: J1.102 J12.8
DSI1_CP: J1.100 J12.9(P9)
DSI1_DN0: J1.96 J12.2
DSI1_DN1: J1.120 J12.5
DSI1_DN2: J1.114 J12.11
DSI1_DN3: J1.108 J12.14
DSI1_DP0: J1.94 J12.3
DSI1_DP1: J1.118 J12.6
DSI1_DP2: J1.112 J12.12
DSI1_DP3: J1.106 J12.15
EMMC_DISABLE_N: J1.2 Q1.3
EMMC_EN_N_1V8: J1.90 Q2.1 R10.2
GPIO0: J1.3 J5.1
GPIO0-27_VREF: C13.1 J1.39 J1.40 R7.1
GPIO1: J1.5 J5.3
GPIO2: J1.9 J5.5
GPIO3: J1.11 J5.7
GPIO4: J1.15 J5.9(P9)
GPIO5: J1.17 J5.11
GPIO6: J1.21 J5.13
GPIO7: J1.23 J5.15
GPIO8: J1.27 J5.17
GPIO9: J1.29 J5.19
GPIO10: J1.33 J5.21
GPIO11: J1.35 J5.23
GPIO12: J1.45 J5.25
GPIO13: J1.47 J5.27
GPIO14: J1.51 J5.29
GPIO15: J1.53 J5.31
GPIO16: J1.57 J5.33
GPIO17: J1.59 J5.35
GPIO18: J1.63 J5.37
GPIO19: J1.65 J5.39
GPIO20: J1.69 J5.41
GPIO21: J1.71 J5.43
GPIO22: J1.75 J5.45
GPIO23: J1.77 J5.47
GPIO24: J1.81 J5.49
GPIO25: J1.83 J5.51
GPIO26: J1.87 J5.53
GPIO27: J1.89 J5.55
GPIO28: J1.28 J6.1 R27.1
GPIO28-45_VREF: C14.1 J1.41 J1.42 R8.1
GPIO29: J1.30 J6.3 R26.1
GPIO30: J1.34 J6.5
GPIO31: J1.36 J6.7
GPIO32: J1.46 J6.9(P9)
GPIO33: J1.48 J6.11
GPIO34: J1.52 J6.13
GPIO35: J1.54 J6.15
GPIO36: J1.58 J6.17
GPIO37: J1.60 J6.19
GPIO38: J1.64 J6.21
GPIO39: J1.66 J6.23
GPIO40: J1.70 J6.25
GPIO41: J1.72 J6.27
GPIO42: J1.76 J6.29
GPIO43: J1.78 J6.31
GPIO44: J1.82 J6.33 R29.1
GPIO45: J1.84 J6.35 R28.1
H5V: C16.1 J13.18 PP10.1 Q3.1 U3.2(OUT) U4.A1 U4.C1
HDMI_CEC: J1.171 Q3.2(S) R15.1
HDMI_CK_N: J1.111 J13.12
HDMI_CK_P: J1.113 J13.10
HDMI_D0_N: J1.117 J13.9
HDMI_D0_P: J1.119 J13.7
HDMI_D1_N: J1.123 J13.6
HDMI_D1_P: J1.125 J13.4
HDMI_D2_N: J1.129 J13.3
HDMI_D2_P: J1.131 J13.1
HDMI_HPD: J13.19 Q4.1 U4.C3
HDMI_HPD_N_1V8: J1.88 Q4.3 R18.2
HDMI_SCL: J1.175 J13.15 U4.A3
HDMI_SDA: J1.173 J13.16 U4.B3(SDA)
RUN: J1.177 J5.57 J7.1
SDX_CLK: J1.10 J16.5 PP15.1
SDX_CMD: J1.12 J16.3 PP14.1
SDX_D0: J1.16 J16.7 PP16.1
SDX_D1: J1.18 J16.8 PP17.1
SDX_D2: J1.22 J16.1 PP12.1
SDX_D3: J1.24 J16.2 PP13.1
SDX_VREF: C23.1 J1.4 J1.6 R31.1
TVDAC: J1.166 J6.59
USB_DM: J1.167 U5.2
USB_DP: J1.165 U5.1
USB_OTGID: J1.168 J6.55 R12.2
USBA_DM: J14.2 U5.6
USBA_DP: J14.3 U5.7
USBB_DM: J15.2 U5.4
USBB_DP: J15.3 U5.5
VC_TCK: J1.180 J7.8(P8)
VC_TDI: J1.174 J7.3
VC_TDO: J1.178 J7.5
VC_TMS: J1.176 J7.6
VC_TRST_N: J1.172 J7.2
VG0: J3.3 J5.16 J5.28 J5.40 J5.52 R7.2
VG1: J3.4 J6.16 J6.28 J6.40 J6.52 R8.2
N1195355: D2.2 PP9.1 R9.2
N1195439: D2.1(CATHODE) Q1.2(S) Q2.3
N1202496: C6.1 R2.2 U1.12
N1202592: L1.1 U1.8
N1202604: L2.1 U1.2
N1202780: F1.1 J2.1 PP1.1
N1203166: C9.1 U2.4
N1203318: D1.2 PP7.1 R3.2
N1313759: C21.2 R22.2 R25.1 U1.4
N1313939: C22.2 R23.2 R24.1 U1.10
N1329395: PP11.1 Q5.3 R20.2 U5.10
N1357591: J4.2 Q1.1 R30.1

Pads without a net: J1 124 126 128 130 132 154 156 158 160 162; J2 2 3 4; J5 59; J9 11 12 14 15; J10 11 12 14 15 17 18; J12 17 18; J13 14; J15 4; J16 9 10; U1 5 11; U4 B1

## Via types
v1: diameter 0.5, hole 0.25, TOP to BOTTOM, 476 vias

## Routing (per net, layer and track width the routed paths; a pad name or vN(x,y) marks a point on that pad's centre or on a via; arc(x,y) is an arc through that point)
1V8: length 64.9
  TOP w0.2: R18.1 10.46,62.48 v1(9.95,62.99) ; R10.1 79.98,9.99 v1(79.98,9.31) ; 63.67,8.68 63.7,8.65 ; R23.1 C22.1
  TOP w0.3: v1(58.1,13.1) 58.95,13.95 61.9,13.95 63.7,12.15 C22.1 63.7,8.65
  TOP w0.5: v1(39,18.15) R5.1 v1(37.9,19.05) ; C12.1 v1(58.1,13.1)
  TOP w1: C12.1 58.08,12.03 L2.2
  PWRT w0.2: 80,12.45 79.98,12.43 v1(79.98,9.31)
  PWRT w0.215: 79.67,49.65 J5.36 ; J5.36 80.77,48.55 ; J5.36 80.77,50.75 ; 79.67,34.41 J5.48 ; J5.48 80.77,35.51 ; J5.48 80.77,33.31 ; J6.48 68.07,35.51 ; J6.48 69.17,34.41 ; J6.48 68.07,33.31 ; J6.48 66.97,34.41 ; 68.07,63.79 J6.24 ; J6.24 66.97,64.89 ; J6.24 68.07,65.99 ; J6.24 69.17,64.89 ; 63.36,99.23 J3.6 ; J3.6 64.46,98.13 ; J3.6 65.56,99.23 ; J3.6 64.46,100.33 ; 79.67,80.13 J5.12 ; J5.12 80.77,79.03 ; J5.12 80.77,81.23 ; J3.5 64.46,102.87 ; J3.5 65.56,101.77 ; J3.5 63.36,101.77 ; J6.12 68.07,81.23 ; J6.12 68.07,79.03 ; J6.12 69.17,80.13 ; J6.12 66.97,80.13 ; J5.24 80.77,65.99 ; J5.24 79.67,64.89 ; J5.24 80.77,63.79 ; J6.36 69.17,49.65 ; J6.36 66.97,49.65 ; J6.36 68.07,48.55 ; J6.36 68.07,50.75
  PWRT w0.3: 64.5,100.5 64.46,100.54 J3.5
  BOTTOM w0.5: PP6.1 58.1,11.9 v1(58.1,13.1)
3V3: length 79.3
  TOP w0.2: J10.22 v1(4.12,75.25) ; R17.1 v1(5.7,95.87) ; 7,76.48 R14.1 v1(7,77.14) ; 56.37,6.35 56.4,6.32 ; 15.48,56 R15.2 v1(16.14,56) ; v1(27.65,20.09) 27.65,20.8 C17.2 U5.9 ; 55.3,6.32 56.4,6.32 ; J12.22 v1(4.12,93.25) ; J11.22 v1(5.88,40.25) ; J9.22 v1(4.12,22.25) ; v1(7.76,8.5) R20.1 8.42,8.5 ; R16.1 v1(6.8,95.87) ; v1(8,77.15) R13.1 8,76.48
  TOP w0.3: v1(49,7) 49,6.38 ; v1(60.9,1.9) 58.2,1.9 56.4,3.7 56.4,6.32 ; U2.3 v1(40.78,12.35) ; C4.1 38.66,13.65 U2.1 v1(40.78,13.65) ; v1(47.8,7) 47.8,6.38
  TOP w0.5: v1(14.7,103.9) J16.4 v1(14.7,102) ; v1(34,18.15) R4.1 v1(35.1,19.05) ; v1(23.4,101.8) C24.1 v1(22.5,102.67) ; R31.2 v1(21.62,96) ; C11.1 v1(60.9,1.9)
  TOP w1: L1.2 63.98,3 C11.1
  PWRB w0.215: J5.44 80.77,40.59 ; J5.44 80.77,38.39 ; J5.44 81.87,39.49 ; J5.44 79.67,39.49 ; J6.32 68.07,55.83 ; J6.32 66.97,54.73 ; J6.32 69.17,54.73 ; J6.32 68.07,53.63 ; 68.07,68.87 J6.20 ; J6.20 66.97,69.97 ; J6.20 68.07,71.07 ; J6.20 69.17,69.97 ; 79.67,69.97 J5.20 ; J5.20 80.77,68.87 ; J5.20 80.77,71.07 ; J5.20 81.87,69.97 ; J3.2 69.54,100.33 ; J3.2 69.54,98.13 ; J3.2 70.64,99.23 ; J3.2 68.44,99.23 ; J5.32 81.87,54.73 ; J5.32 79.67,54.73 ; J5.32 80.77,55.83 ; J5.32 80.77,53.63 ; 68.07,84.11 J6.8 ; J6.8 66.97,85.21 ; J6.8 69.17,85.21 ; J6.8 68.07,86.31 ; J5.8 81.87,85.21 ; J5.8 79.67,85.21 ; J5.8 80.77,86.31 ; J5.8 80.77,84.11 ; 68.44,101.77 J3.1 ; J3.1 69.54,100.67 ; J3.1 70.64,101.77 ; J6.44 68.07,40.59 ; J6.44 69.17,39.49 ; J6.44 66.97,39.49 ; J6.44 68.07,38.39
  BOTTOM w0.5: PP2.1 60.9,3.1 v1(60.9,1.9)
5V: length 46.2
  TOP w0.2: v1(62.18,10.39) 62.18,9.71 R2.1 ; U1.6 v1(57.8,5.87)
  TOP w0.3: C8.1 57.8,9.7 U1.1 ; U1.7 61.2,5.3 C7.1 ; v1(11.6,60.14) C15.1 11.6,59.45
  TOP w0.4: v1(11.6,60.14) 13.64,60.14 U3.3 ; v1(68.92,11.6) F1.2 v1(71,10.47) ; v1(74.5,10.05) C2.1 v1(75.78,11)
  TOP w0.5: C8.1 57.3,10 v1(57.1,10.2) ; R19.1 v1(42,1.65) ; v1(61.9,4.8) 61.7,5 C7.1
  TOP w1: v1(37.4,10.1) 37.4,11.97 31.5,17.88 R1.1
  PWRT w0.215: 80.77,89.19 J5.4 ; J5.4 81.87,90.29 ; J5.4 79.67,90.29 ; J5.4 80.77,91.39 ; J5.56 81.87,24.25 ; J5.56 79.67,24.25 ; J5.56 80.77,23.15 ; J5.56 80.77,25.35 ; J6.4 68.07,91.39 ; J6.4 68.07,89.19 ; J6.4 69.17,90.29 ; J6.4 66.97,90.29 ; J6.56 69.17,24.25 ; J6.56 66.97,24.25 ; J6.56 68.07,23.15 ; J6.56 68.07,25.35
  BOTTOM w0.5: v1(71,10.47) PP3.1
GND: length 1063.6
  TOP w0.2: J9.10 v1(5.88,16.25) ; v1(57.2,21.06) R12.1 57.2,21.72 ; 54.2,6.32 v1(54.2,5.66) ; J12.4 v1(5.88,84.25) ; J11.7 v1(5.88,32.75) ; J10.10 v1(5.88,69.25) ; 33.22,62.85 R29.2 v1(32.48,62.85) ; v1(11.42,50) J13.5 v1(8.06,50) ; J9.13 v1(4.12,17.75) ; C6.2 62.15,11.29 v1(62.15,11.94) ; U4.B2 U4.C2 v1(12.5,56.42) ; v1(7.76,9.5) R21.2 8.42,9.5 ; J10.16 v1(5.88,72.25) ; Q2.2 v1(81.98,10) ; J10.7 v1(5.88,67.75) ; 33.22,80.85 R26.2 v1(32.48,80.85) ; v1(8.06,48.5) J13.2 v1(11.42,48.5) ; J11.4 v1(5.88,31.25) ; J9.4 v1(5.88,13.25) ; U5.3 24.2,21.2 v1(24,21.4) ; Q5.2 v1(10.4,10.58) ; J12.1 v1(5.88,82.75) ; v1(64.8,9.34) R24.2 64.8,8.68 ; v1(8.06,51.5) J13.8 v1(11.42,51.5) ; v1(39.55,60.95) 39.45,61.05 R28.2 38.43,61.05 ; J10.1 v1(5.88,64.75) ; v1(6.95,60.9) 7.55,61.5 Q4.2 ; v1(11.42,53) J13.11 v1(8.06,53) ; J10.19 v1(5.88,73.75) ; J12.10 v1(5.88,87.25) ; J10.13 v1(5.88,70.75) ; U5.8 26.95,20.4 ; J11.13 v1(5.88,35.75) ; J11.10 v1(5.88,34.25) ; v1(11.42,56) J13.17 v1(8.06,56) ; J12.7 v1(5.88,85.75) ; J9.7 v1(5.88,14.75) ; J9.1 v1(5.88,11.75) ; J12.19 v1(5.88,91.75) ; J12.13 v1(5.88,88.75) ; J11.16 v1(5.88,37.25) ; J9.16 v1(5.88,19.25) ; J10.4 v1(5.88,66.25) ; J12.16 v1(5.88,90.25) ; v1(29.55,99) J7.7 ; J11.1 v1(5.88,29.75) ; J9.19 v1(5.88,20.75) ; J11.19 v1(5.88,38.75)
  TOP w0.215: 79.72,26.79 J5.54 ; J5.54 80.77,27.84 ; J5.54 81.82,26.79 ; J5.54 80.77,25.74 ; Q2.2 81.2,10.38 ; Q2.2 80.6,10 ; Q2.2 81.2,9.62 ; J5.26 80.77,63.4 ; J5.26 79.72,62.35 ; J5.26 80.77,61.3 ; J5.26 81.82,62.35 ; R30.2 82.97,14.6 ; R30.2 82.48,14.11 ; R30.2 82.48,15.09 ; 68.07,40.98 J6.42 ; J6.42 68.07,43.08 ; J6.42 69.12,42.03 ; J6.42 67.02,42.03 ; 7.08,59.75 J13.22 ; J13.22 10.88,59.75 ; J13.22 8.98,60.75 ; J13.22 8.98,58.75 ; 12.09,58.52 C15.2 11.11,58.52 ; 35.9,2 C19.2 38.1,2 ; 22.02,98 C23.2 ; C23.2 22.7,97.3 ; C23.2 23.38,98 ; C23.2 22.7,98.7 ; 16.89,102.2 J16.6 16.89,103.7 ; J6.18 68.07,73.56 ; J6.18 68.07,71.46 ; J6.18 69.12,72.51 ; J6.18 67.02,72.51 ; J5.30 81.82,57.27 ; J5.30 80.77,58.32 ; J5.30 79.72,57.27 ; J5.30 80.77,56.22 ; 38.4,2 C20.2 40.6,2 ; U3.1 13.38,57.7 ; U3.1 12.85,56.95 ; U3.1 12.32,57.7 ; 68.07,66.38 J6.22 ; J6.22 68.07,68.48 ; J6.22 69.12,67.43 ; J6.22 67.02,67.43 ; 32.73,82.65 R27.2 33.22,83.14 ; 79.72,52.19 J5.34 ; J5.34 80.77,53.24 ; J5.34 80.77,51.14 ; J5.34 81.82,52.19 ; 68.07,18.12 J6.60 ; J6.60 69.12,19.17 ; J6.60 67.02,19.17 ; J6.60 68.07,20.22 ; D1.1 51.88,2 ; D1.1 51.2,2.7 ; D1.1 51.2,1.3 ; 19.86,78.75 19.86,79.24 ; 19.86,78.75 19.86,78.26 ; 19.86,78.75 19.38,78.75 ; 67.02,82.67 J6.10 ; J6.10 68.07,83.72 ; J6.10 69.12,82.67 ; J6.10 68.07,81.62 ; 8.94,101.95 8.94,102.83 ; 8.94,102.83 7.96,102.83 ; 8.94,102.83 9.91,102.83 ; 8.94,102.83 8.94,103.7 ; J6.6 68.07,88.8 ; J6.6 67.02,87.75 ; J6.6 68.07,86.7 ; J6.6 69.12,87.75 ; 80.77,40.98 J5.42 ; J5.42 80.77,43.08 ; J5.42 81.82,42.03 ; J5.42 79.72,42.03 ; J5.14 81.82,77.59 ; J5.14 80.77,76.54 ; J5.14 80.77,78.64 ; J5.14 79.72,77.59 ; J5.2 81.82,92.83 ; J5.2 80.77,93.88 ; J5.2 79.72,92.83 ; J5.2 80.77,91.78 ; J13.21 4.42,45.25 ; J13.21 3.02,46.25 ; J13.21 1.62,45.25 ; J13.21 3.02,44.25 ; 15.51,59.48 C16.2 16,59.97 ; C24.2 23.2,100.2 ; C24.2 22.5,99.52 ; C24.2 22.5,100.88 ; C24.2 21.8,100.2 ; 5,29.4 J11.1 4.3,29.75 ; 79.72,21.71 J5.58 ; J5.58 80.77,20.66 ; J5.58 81.82,21.71 ; J5.58 80.77,22.76 ; 19.95,8.79 J14.5 ; J14.5 23.91,8.79 ; J14.5 21.93,6.81 ; J14.5 21.93,10.77 ; C1.2 17,28.1 ; C1.2 17.78,27 ; C1.2 17,25.9 ; C1.2 16.22,27 ; 21.7,90.15 J1.1 24.1,90.15 ; 80.77,86.7 J5.6 ; J5.6 79.72,87.75 ; J5.6 80.77,88.8 ; J5.6 81.82,87.75 ; 16,8.41 J4.3 ; J4.3 16,10.51 ; J4.3 17.05,9.46 ; J4.3 14.95,9.46 ; J6.46 68.07,38 ; J6.46 67.02,36.95 ; J6.46 68.07,35.9 ; J6.46 69.12,36.95 ; J6.58 68.07,22.76 ; J6.58 68.07,20.66 ; J6.58 67.02,21.71 ; J6.58 69.12,21.71 ; J13.20 10.88,45.25 ; J13.20 8.98,44.25 ; J13.20 7.08,45.25 ; J13.20 8.98,46.25 ; 68.07,46.06 J6.38 ; J6.38 69.12,47.11 ; J6.38 67.02,47.11 ; J5.10 81.82,82.67 ; J5.10 79.72,82.67 ; J5.10 80.77,83.72 ; J5.10 80.77,81.62 ; 68.07,56.22 J6.30 ; J6.30 69.12,57.27 ; J6.30 67.02,57.27 ; J6.30 68.07,58.32 ; 80.77,18.12 J5.60 ; J5.60 79.72,19.17 ; J5.60 80.77,20.22 ; J5.60 81.82,19.17 ; J5.46 80.77,38 ; J5.46 80.77,35.9 ; J5.46 79.72,36.95 ; J5.46 81.82,36.95 ; 79.72,47.11 J5.38 ; J5.38 80.77,46.06 ; J5.38 80.77,48.16 ; J5.38 81.82,47.11 ; J13.23 3.02,60.75 ; J13.23 1.62,59.75 ; J13.23 4.42,59.75 ; J13.23 3.02,58.75 ; 8.2,61.12 Q4.2 ; Q4.2 8.8,61.5 ; Q4.2 8.2,61.88 ; 79.72,72.51 J5.18 ; J5.18 80.77,73.56 ; J5.18 81.82,72.51 ; J5.18 80.77,71.46 ; 79.72,67.43 J5.22 ; J5.22 80.77,66.38 ; J5.22 81.82,67.43 ; J5.22 80.77,68.48 ; C17.1 28.59,21.29 ; C17.1 29.07,20.8 ; C17.1 28.59,20.31 ; C3.2 17,30.6 ; C3.2 16.22,29.5 ; C3.2 17.78,29.5 ; C3.2 17,28.4 ; 16.43,6.01 J15.8 18.15,5.03 ; J6.54 68.07,27.84 ; J6.54 69.12,26.79 ; J6.54 68.07,25.74 ; J6.54 67.02,26.79 ; 20.25,101.5 J16.11 ; J16.11 21.04,102.6 ; J16.11 20.25,103.7 ; J6.50 68.07,32.92 ; J6.50 67.02,31.87 ; J6.50 69.12,31.87 ; J6.50 68.07,30.82 ; 77.15,5.03 J2.8 75.42,6.01 ; 65.53,20.66 J6.57 ; J6.57 64.48,21.71 ; J6.57 65.53,22.76 ; J6.57 66.58,21.71 ; J14.4 33,11.5 ; J14.4 31,11.5 ; J14.4 32,12.5 ; J14.4 32,10.5 ; J6.14 69.12,77.59 ; J6.14 67.02,77.59 ; J6.14 68.07,76.54 ; J6.14 68.07,78.64 ; 35.07,6.81 J14.6 ; J14.6 33.09,8.79 ; J14.6 37.05,8.79 ; J14.6 35.07,10.77 ; 9.85,5.03 J15.6 11.57,6.01 ; 79.72,31.87 J5.50 ; J5.50 80.77,32.92 ; J5.50 80.77,30.82 ; J5.50 81.82,31.87 ; 17.08,92.15 J16.14 ; J16.14 18.23,91.27 ; J16.14 18.23,93.03 ; J16.14 19.38,92.15 ; J16.13 13.41,92.15 ; J16.13 12.26,93.03 ; J16.13 12.26,91.27 ; J16.13 11.11,92.15 ; 17,30.9 C10.2 ; C10.2 17,33.1 ; C10.2 16.22,32 ; C10.2 17.78,32 ; 56.71,21.71 R12.1 57.69,21.71 ; 67.02,92.83 J6.2 ; J6.2 68.07,91.78 ; J6.2 69.12,92.83 ; J6.2 68.07,93.88 ; 4.3,82.75 J12.1 5,82.4 ; 68.07,51.14 J6.34 ; J6.34 69.12,52.19 ; J6.34 67.02,52.19 ; J6.34 68.07,53.24 ; C4.2 38.99,12.52 ; C4.2 38.01,12.52 ; C4.2 38.5,12.03 ; 31.05,100.8 J7.4 31.05,99.2 ; 40.2,14.3 C5.2 ; C5.2 40.2,15.7 ; C5.2 40.88,15 ; 19.86,74.55 19.86,75.04 ; 19.86,74.55 19.86,74.06 ; 19.86,74.55 19.38,74.55 ; J6.26 69.12,62.35 ; J6.26 67.02,62.35 ; J6.26 68.07,61.3 ; J6.26 68.07,63.4 ; 73.4,8 C2.2 74.5,8.78 ; C9.2 40.52,11.69 ; C9.2 40.52,10.71 ; C9.2 40.03,11.2 ; 5,11.4 J9.1 4.3,11.75 ; 10.78,9.8 Q5.2 10.02,9.8 ; 68.85,5.03 J2.6 70.58,6.01
  TOP w0.25: U1.9 59.73,7.28 U1.13 59.27,7.72 U1.3
  TOP w0.3: 19.9,74.55 v1(19.9,73.86) ; J1.145 v1(21.52,43.35) ; J1.8 v1(29.7,88.05) 29.65,88.05 ; J1.196 v1(29.72,28.05) ; J1.116 v1(32.48,52.05) ; J1.139 v1(21.52,45.15) ; J1.151 v1(21.52,41.55) ; J1.181 v1(21.52,32.55) ; J1.61 v1(21.52,68.55) ; J1.188 v1(29.72,30.45) ; J1.122 v1(32.48,50.25) ; J1.56 v1(32.48,70.05) ; J1.85 v1(21.52,61.35) ; J1.73 v1(21.52,64.95) ; J1.13 v1(21.52,86.55) ; 11.6,58.55 C15.2 v1(11.6,57.86) ; J1.7 v1(21.52,88.35) ; J1.97 v1(21.52,57.75) ; J1.103 v1(21.52,55.95) ; J1.157 v1(21.52,39.75) ; J1.195 v1(24.28,28.35) ; J1.133 v1(21.52,46.95) ; J1.44 v1(32.48,73.65) ; 38.5,12.55 38.7,12.55 39.15,13 U2.2 v1(40.78,13) ; D1.1 v1(50.35,2) ; J1.146 v1(32.48,43.05) ; J1.163 v1(21.52,37.95) ; U3.1 v1(12.85,58.63) ; J1.115 v1(21.52,52.35) ; J1.152 v1(32.48,41.25) ; J1.109 v1(21.52,54.15) ; J1.91 v1(21.52,59.55) ; J1.98 v1(32.48,57.45) ; J1.169 v1(21.52,36.15) ; J1.62 v1(32.48,68.25) ; 19.9,78.75 v1(19.9,79.44) ; v1(22.9,90.8) J1.1 ; J1.170 v1(32.48,35.85) ; J1.187 v1(24.28,30.75) ; J1.49 v1(21.52,72.15) ; J1.121 v1(21.52,50.55) ; J1.164 v1(32.48,37.65) ; J1.67 v1(21.52,66.75) ; J1.86 v1(32.48,61.05) ; J1.110 v1(32.48,53.85) ; J1.19 v1(21.52,84.75) ; J1.74 v1(32.48,64.65) ; J1.50 v1(32.48,71.85) ; J1.32 v1(32.48,80.85) ; J1.55 v1(21.52,70.35) ; J1.80 v1(32.48,62.85) ; J1.182 v1(32.48,32.25) ; J1.26 v1(32.48,82.65) ; J1.140 v1(32.48,44.85) ; C5.2 v1(39.35,15) ; J1.37 v1(21.52,79.35) ; J1.14 v1(32.5,86.25) ; J1.25 v1(21.52,82.95) ; J1.134 v1(32.48,46.65) ; J1.43 v1(21.52,73.95) ; J1.68 v1(32.48,66.45) ; J1.38 v1(32.48,79.05) ; J1.20 v1(32.5,84.45) ; J1.104 v1(32.48,55.65) ; J1.31 v1(21.52,81.15) ; J1.79 v1(21.52,63.15) ; J1.92 v1(32.48,59.25) ; J1.127 v1(21.52,48.75)
  TOP w0.4: v1(75.78,8) C2.2 v1(74.5,7.05) ; J15.5 v1(15.3,6.08) ; J2.5 v1(74.3,6.1)
  TOP w0.5: v1(37,1.05) C19.2 v1(37,2.95) ; v1(39.5,2.95) C20.2 v1(39.5,1.05)
  GNDT w0.215: J5.60 81.87,19.17 ; J5.60 80.77,20.27 ; J5.60 80.77,18.07 ; J5.60 79.67,19.17 ; J4.3 16,10.56 ; J4.3 16,8.36 ; J4.3 17.1,9.46 ; J4.3 14.9,9.46 ; 35.07,6.76 J14.6 ; J14.6 37.1,8.79 ; J14.6 33.04,8.79 ; J14.6 35.07,10.82 ; 80.77,40.93 J5.42 ; J5.42 79.67,42.03 ; J5.42 81.87,42.03 ; J5.42 80.77,43.13 ; J13.23 3.02,60.8 ; J13.23 1.57,59.75 ; J13.23 3.02,58.7 ; J13.23 4.47,59.75 ; 16.43,4 J15.8 ; J15.8 15.6,5.03 ; J15.8 16.43,6.06 ; J15.8 17.25,5.03 ; 66.97,36.95 J6.46 ; J6.46 69.17,36.95 ; J6.46 68.07,38.05 ; J6.46 68.07,35.85 ; J13.20 8.98,46.3 ; J13.20 8.98,44.2 ; J13.20 10.93,45.25 ; J13.20 7.03,45.25 ; J13.21 3.02,46.3 ; J13.21 1.57,45.25 ; J13.21 3.02,44.2 ; J13.21 4.47,45.25 ; 10.42,2 J15.7 ; J15.7 11.28,3.2 ; J15.7 11.28,0.8 ; J15.7 12.13,2 ; 68.07,91.73 J6.2 ; J6.2 69.17,92.83 ; J6.2 68.07,93.93 ; J6.2 66.97,92.83 ; 68.07,46.01 J6.38 ; J6.38 66.97,47.11 ; J6.38 68.07,48.21 ; J6.38 69.17,47.11 ; J2.7 71.13,2 ; J2.7 69.42,2 ; J2.7 70.28,0.8 ; J2.7 70.28,3.2 ; J5.54 80.77,27.89 ; J5.54 81.87,26.79 ; J5.54 79.67,26.79 ; J5.54 80.77,25.69 ; J2.8 76.25,5.03 ; J2.8 75.42,4 ; J2.8 75.42,6.06 ; J2.8 74.6,5.03 ; J6.50 69.17,31.87 ; J6.50 68.07,30.77 ; J6.50 68.07,32.97 ; J6.50 66.97,31.87 ; J6.22 69.17,67.43 ; J6.22 66.97,67.43 ; J6.22 68.07,66.33 ; J6.22 68.07,68.53 ; J5.34 80.77,53.29 ; J5.34 79.67,52.19 ; J5.34 80.77,51.09 ; J5.34 81.87,52.19 ; 66.97,72.51 J6.18 ; J6.18 68.07,71.41 ; J6.18 68.07,73.61 ; J6.18 69.17,72.51 ; 32,10.45 J14.4 ; J14.4 32,12.55 ; J14.4 30.95,11.5 ; J14.4 33.05,11.5 ; J2.6 70.58,6.06 ; J2.6 69.75,5.03 ; J2.6 71.4,5.03 ; J2.6 70.58,4 ; J6.14 68.07,78.69 ; J6.14 66.97,77.59 ; J6.14 68.07,76.49 ; J6.14 69.17,77.59 ; J6.30 69.17,57.27 ; J6.30 66.97,57.27 ; J6.30 68.07,58.37 ; J6.30 68.07,56.17 ; 80.77,81.57 J5.10 ; J5.10 81.87,82.67 ; J5.10 79.67,82.67 ; J5.10 80.77,83.77 ; J6.60 69.17,19.17 ; J6.60 68.07,18.07 ; J6.60 68.07,20.27 ; J6.60 66.97,19.17 ; 75.72,0.8 J2.9 ; J2.9 75.72,3.2 ; J2.9 76.58,2 ; J2.9 74.87,2 ; J13.22 8.98,60.8 ; J13.22 10.93,59.75 ; J13.22 8.98,58.7 ; J13.22 7.03,59.75 ; 68.07,81.57 J6.10 ; J6.10 66.97,82.67 ; J6.10 69.17,82.67 ; J6.10 68.07,83.77 ; 80.77,76.49 J5.14 ; J5.14 80.77,78.69 ; J5.14 81.87,77.59 ; J5.14 79.67,77.59 ; J5.6 81.87,87.75 ; J5.6 80.77,86.65 ; J5.6 80.77,88.85 ; J5.6 79.67,87.75 ; J15.6 11.57,6.06 ; J15.6 12.4,5.03 ; J15.6 10.75,5.03 ; J15.6 11.57,4 ; J5.18 81.87,72.51 ; J5.18 80.77,73.61 ; J5.18 79.67,72.51 ; J5.18 80.77,71.41 ; 19.9,8.79 J14.5 ; J14.5 21.93,10.82 ; J14.5 23.96,8.79 ; J14.5 21.93,6.76 ; J5.26 81.87,62.35 ; J5.26 79.67,62.35 ; J5.26 80.77,61.25 ; J5.26 80.77,63.45 ; 68.07,51.09 J6.34 ; J6.34 66.97,52.19 ; J6.34 69.17,52.19 ; J6.34 68.07,53.29 ; 66.97,87.75 J6.6 ; J6.6 68.07,88.85 ; J6.6 68.07,86.65 ; J6.6 69.17,87.75 ; J5.30 81.87,57.27 ; J5.30 80.77,58.37 ; J5.30 80.77,56.17 ; J5.30 79.67,57.27 ; 80.77,91.73 J5.2 ; J5.2 79.67,92.83 ; J5.2 80.77,93.93 ; J5.2 81.87,92.83 ; 68.07,20.61 J6.58 ; J6.58 68.07,22.81 ; J6.58 66.97,21.71 ; J6.58 69.17,21.71 ; J6.57 66.63,21.71 ; J6.57 65.53,22.81 ; J6.57 65.53,20.61 ; J6.57 64.43,21.71 ; J5.38 81.87,47.11 ; J5.38 79.67,47.11 ; J5.38 80.77,48.21 ; J5.38 80.77,46.01 ; J5.22 80.77,68.53 ; J5.22 79.67,67.43 ; J5.22 81.87,67.43 ; J5.22 80.77,66.33 ; 66.97,42.03 J6.42 ; J6.42 68.07,43.13 ; J6.42 69.17,42.03 ; J6.42 68.07,40.93 ; J6.26 69.17,62.35 ; J6.26 68.07,63.45 ; J6.26 68.07,61.25 ; J6.26 66.97,62.35 ; J5.58 81.87,21.71 ; J5.58 80.77,20.61 ; J5.58 79.67,21.71 ; J5.58 80.77,22.81 ; 80.77,30.77 J5.50 ; J5.50 81.87,31.87 ; J5.50 80.77,32.97 ; J5.50 79.67,31.87 ; J5.46 80.77,38.05 ; J5.46 81.87,36.95 ; J5.46 79.67,36.95 ; J5.46 80.77,35.85 ; 68.07,25.69 J6.54 ; J6.54 68.07,27.89 ; J6.54 66.97,26.79 ; J6.54 69.17,26.79 ; J15.9 16.73,3.2 ; J15.9 15.87,2 ; J15.9 17.58,2 ; J15.9 16.73,0.8
  GNDB w0.215: J2.8 76.25,5.03 ; J2.8 74.6,5.03 ; J2.8 75.42,6.06 ; J2.8 75.42,4 ; J6.14 69.17,77.59 ; J6.14 68.07,78.69 ; J6.14 68.07,76.49 ; J6.14 66.97,77.59 ; J6.6 68.07,88.85 ; J6.6 69.17,87.75 ; J6.6 66.97,87.75 ; J6.6 68.07,86.65 ; J5.38 81.87,47.11 ; J5.38 80.77,46.01 ; J5.38 79.67,47.11 ; J5.38 80.77,48.21 ; 80.77,56.17 J5.30 ; J5.30 80.77,58.37 ; J5.30 79.67,57.27 ; J5.30 81.87,57.27 ; J6.57 66.63,21.71 ; J6.57 65.53,20.61 ; J6.57 65.53,22.81 ; J6.57 64.43,21.71 ; J5.2 81.87,92.83 ; J5.2 80.77,93.93 ; J5.2 80.77,91.73 ; J5.2 79.67,92.83 ; 68.07,71.41 J6.18 ; J6.18 68.07,73.61 ; J6.18 66.97,72.51 ; J6.18 69.17,72.51 ; 10.75,5.03 J15.6 ; J15.6 11.57,6.06 ; J15.6 12.4,5.03 ; J15.6 11.57,4 ; J6.60 69.17,19.17 ; J6.60 66.97,19.17 ; J6.60 68.07,18.07 ; J6.60 68.07,20.27 ; 16,8.36 J4.3 ; J4.3 17.1,9.46 ; J4.3 16,10.56 ; J4.3 14.9,9.46 ; J6.22 68.07,68.53 ; J6.22 68.07,66.33 ; J6.22 66.97,67.43 ; J6.22 69.17,67.43 ; J5.60 81.87,19.17 ; J5.60 80.77,18.07 ; J5.60 79.67,19.17 ; J5.60 80.77,20.27 ; 1.57,59.75 J13.23 ; J13.23 3.02,58.7 ; J13.23 4.47,59.75 ; J13.23 3.02,60.8 ; J5.54 81.87,26.79 ; J5.54 80.77,27.89 ; J5.54 80.77,25.69 ; J5.54 79.67,26.79 ; J6.42 69.17,42.03 ; J6.42 68.07,43.13 ; J6.42 66.97,42.03 ; J6.42 68.07,40.93 ; 68.07,91.73 J6.2 ; J6.2 66.97,92.83 ; J6.2 69.17,92.83 ; J6.2 68.07,93.93 ; J15.8 17.25,5.03 ; J15.8 16.43,6.06 ; J15.8 15.6,5.03 ; J15.8 16.43,4 ; 70.58,4 J2.6 ; J2.6 71.4,5.03 ; J2.6 69.75,5.03 ; J2.6 70.58,6.06 ; 1.57,45.25 J13.21 ; J13.21 3.02,46.3 ; J13.21 3.02,44.2 ; J13.21 4.47,45.25 ; 66.97,47.11 J6.38 ; J6.38 69.17,47.11 ; J6.38 68.07,46.01 ; J6.38 68.07,48.21 ; J5.58 81.87,21.71 ; J5.58 79.67,21.71 ; J5.58 80.77,20.61 ; J5.58 80.77,22.81 ; J15.7 12.13,2 ; J15.7 11.28,3.2 ; J15.7 10.42,2 ; J15.7 11.28,0.8 ; J13.20 8.98,46.3 ; J13.20 10.93,45.25 ; J13.20 7.03,45.25 ; J13.20 8.98,44.2 ; 19.9,8.79 J14.5 ; J14.5 23.96,8.79 ; J14.5 21.93,10.82 ; J14.5 21.93,6.76 ; 80.77,76.49 J5.14 ; J5.14 80.77,78.69 ; J5.14 81.87,77.59 ; J5.14 79.67,77.59 ; J13.22 10.93,59.75 ; J13.22 7.03,59.75 ; J13.22 8.98,58.7 ; J13.22 8.98,60.8 ; 66.97,36.95 J6.46 ; J6.46 69.17,36.95 ; J6.46 68.07,38.05 ; J6.46 68.07,35.85 ; J5.18 81.87,72.51 ; J5.18 79.67,72.51 ; J5.18 80.77,73.61 ; J5.18 80.77,71.41 ; 68.07,20.61 J6.58 ; J6.58 69.17,21.71 ; J6.58 68.07,22.81 ; J6.58 66.97,21.71 ; J6.30 68.07,58.37 ; J6.30 66.97,57.27 ; J6.30 69.17,57.27 ; J6.30 68.07,56.17 ; 80.77,30.77 J5.50 ; J5.50 79.67,31.87 ; J5.50 81.87,31.87 ; J5.50 80.77,32.97 ; J5.22 80.77,68.53 ; J5.22 79.67,67.43 ; J5.22 80.77,66.33 ; J5.22 81.87,67.43 ; J2.7 70.28,3.2 ; J2.7 69.42,2 ; J2.7 70.28,0.8 ; J2.7 71.13,2 ; J5.34 81.87,52.19 ; J5.34 80.77,51.09 ; J5.34 80.77,53.29 ; J5.34 79.67,52.19 ; J14.4 33.05,11.5 ; J14.4 30.95,11.5 ; J14.4 32,12.55 ; J14.4 32,10.45 ; J2.9 76.58,2 ; J2.9 74.87,2 ; J2.9 75.72,3.2 ; J2.9 75.72,0.8 ; J6.34 68.07,53.29 ; J6.34 68.07,51.09 ; J6.34 66.97,52.19 ; J6.34 69.17,52.19 ; J5.10 81.87,82.67 ; J5.10 80.77,81.57 ; J5.10 79.67,82.67 ; J5.10 80.77,83.77 ; J5.42 81.87,42.03 ; J5.42 80.77,43.13 ; J5.42 80.77,40.93 ; J5.42 79.67,42.03 ; 35.07,6.76 J14.6 ; J14.6 33.04,8.79 ; J14.6 35.07,10.82 ; J14.6 37.1,8.79 ; J5.6 80.77,88.85 ; J5.6 80.77,86.65 ; J5.6 79.67,87.75 ; J5.6 81.87,87.75 ; 68.07,81.57 J6.10 ; J6.10 66.97,82.67 ; J6.10 69.17,82.67 ; J6.10 68.07,83.77 ; 16.73,0.8 J15.9 ; J15.9 17.58,2 ; J15.9 16.73,3.2 ; J15.9 15.87,2 ; 80.77,61.25 J5.26 ; J5.26 80.77,63.45 ; J5.26 81.87,62.35 ; J5.26 79.67,62.35 ; 66.97,62.35 J6.26 ; J6.26 69.17,62.35 ; J6.26 68.07,63.45 ; J6.26 68.07,61.25 ; J5.46 81.87,36.95 ; J5.46 80.77,38.05 ; J5.46 80.77,35.85 ; J5.46 79.67,36.95 ; J6.50 69.17,31.87 ; J6.50 68.07,32.97 ; J6.50 68.07,30.77 ; J6.50 66.97,31.87 ; J6.54 69.17,26.79 ; J6.54 68.07,25.69 ; J6.54 66.97,26.79 ; J6.54 68.07,27.89
  BOTTOM w0.215: J5.2 80.77,93.88 ; J5.2 79.72,92.83 ; J5.2 81.82,92.83 ; J5.2 80.77,91.78 ; J5.30 81.82,57.27 ; J5.30 80.77,56.22 ; J5.30 80.77,58.32 ; J5.30 79.72,57.27 ; J13.21 4.42,45.25 ; J13.21 3.02,44.25 ; J13.21 1.62,45.25 ; J13.21 3.02,46.25 ; 7.8,99 PP19.1 ; PP19.1 10.2,99 ; PP19.1 9,100.2 ; PP19.1 9,97.8 ; 79.72,82.67 J5.10 ; J5.10 80.77,83.72 ; J5.10 80.77,81.62 ; J5.10 81.82,82.67 ; 67.02,31.87 J6.50 69.12,31.87 ; J5.22 81.82,67.43 ; J5.22 80.77,66.38 ; J5.22 79.72,67.43 ; J5.22 80.77,68.48 ; 80.77,20.66 J5.58 ; J5.58 80.77,22.76 ; J5.58 81.82,21.71 ; J5.58 79.72,21.71 ; 71.8,2.5 PP8.1 ; PP8.1 74.2,2.5 ; PP8.1 73,3.7 ; PP8.1 73,1.3 ; J14.6 37.05,8.79 ; J14.6 35.07,10.77 ; J14.6 33.09,8.79 ; J14.6 35.07,6.81 ; 80.77,46.06 J5.38 ; J5.38 80.77,48.16 ; J5.38 79.72,47.11 ; J5.38 81.82,47.11 ; J5.18 80.77,73.56 ; J5.18 81.82,72.51 ; J5.18 80.77,71.46 ; J5.18 79.72,72.51 ; PP5.1 77.5,9.7 ; PP5.1 76.3,8.5 ; PP5.1 77.5,7.3 ; PP5.1 78.7,8.5 ; 67.02,52.19 J6.34 69.12,52.19 ; 1.62,59.75 J13.23 ; J13.23 3.02,60.75 ; J13.23 3.02,58.75 ; J13.23 4.42,59.75 ; 69.12,21.71 J6.58 67.02,21.71 ; J2.6 70.58,6.01 ; J2.6 69.8,5.03 ; J2.6 70.58,4.05 ; J2.6 71.35,5.03 ; 67.02,67.43 J6.22 69.12,67.43 ; 11.57,4.05 J15.6 ; J15.6 11.57,6.01 ; J15.6 10.8,5.03 ; J15.6 12.35,5.03 ; J6.2 69.12,92.83 ; J6.2 67.02,92.83 ; J6.2 68.07,93.88 ; 79.72,77.59 J5.14 ; J5.14 81.82,77.59 ; J5.14 80.77,78.64 ; J5.14 80.77,76.54 ; 69.12,72.51 J6.18 67.02,72.51 ; 79.72,36.95 J5.46 ; J5.46 80.77,38 ; J5.46 80.77,35.9 ; J5.46 81.82,36.95 ; 69.12,26.79 J6.54 67.02,26.79 ; 80.77,61.3 J5.26 ; J5.26 81.82,62.35 ; J5.26 80.77,63.4 ; J5.26 79.72,62.35 ; J13.20 8.98,46.25 ; J13.20 7.08,45.25 ; J13.20 10.88,45.25 ; J13.20 8.98,44.25 ; 75.72,0.85 J2.9 ; J2.9 75.72,3.15 ; J2.9 74.92,2 ; J2.9 76.53,2 ; J5.6 80.77,88.8 ; J5.6 81.82,87.75 ; J5.6 79.72,87.75 ; J5.6 80.77,86.7 ; J15.8 17.2,5.03 ; J15.8 15.65,5.03 ; J15.8 16.43,4.05 ; J15.8 16.43,6.01 ; 67.02,19.17 J6.60 ; J6.60 69.12,19.17 ; J6.60 68.07,18.12 ; 67.02,42.03 J6.42 69.12,42.03 ; J15.9 17.53,2 ; J15.9 15.92,2 ; J15.9 16.73,0.85 ; J15.9 16.73,3.15 ; 69.12,77.59 J6.14 67.02,77.59 ; 64.48,21.71 J6.57 66.58,21.71 ; 16,8.41 J4.3 ; J4.3 14.95,9.46 ; J4.3 17.05,9.46 ; J4.3 16,10.51 ; PP18.1 19.7,100.5 ; PP18.1 18.5,99.3 ; PP18.1 17.3,100.5 ; J15.7 12.08,2 ; J15.7 10.47,2 ; J15.7 11.28,0.85 ; J15.7 11.28,3.15 ; 79.72,19.17 J5.60 ; J5.60 81.82,19.17 ; J5.60 80.77,20.22 ; J5.60 80.77,18.12 ; 69.12,62.35 J6.26 67.02,62.35 ; 79.72,31.87 J5.50 ; J5.50 80.77,32.92 ; J5.50 80.77,30.82 ; J5.50 81.82,31.87 ; 69.47,2 J2.7 ; J2.7 70.28,0.85 ; J2.7 70.28,3.15 ; J2.7 71.08,2 ; J5.42 80.77,43.08 ; J5.42 81.82,42.03 ; J5.42 80.77,40.98 ; J5.42 79.72,42.03 ; 69.12,82.67 J6.10 67.02,82.67 ; 69.12,36.95 J6.46 67.02,36.95 ; 69.12,87.75 J6.6 67.02,87.75 ; J14.4 32,12.5 ; J14.4 32,10.5 ; J14.4 31,11.5 ; J14.4 33,11.5 ; 79.72,52.19 J5.34 ; J5.34 81.82,52.19 ; J5.34 80.77,51.14 ; J5.34 80.77,53.24 ; J2.8 75.42,6.01 ; J2.8 75.42,4.05 ; J2.8 76.2,5.03 ; J2.8 74.65,5.03 ; 80.77,25.74 J5.54 ; J5.54 79.72,26.79 ; J5.54 81.82,26.79 ; J5.54 80.77,27.84 ; 8.98,58.75 J13.22 ; J13.22 8.98,60.75 ; J13.22 7.08,59.75 ; J13.22 10.88,59.75 ; 67.02,57.27 J6.30 69.12,57.27 ; 19.95,8.79 J14.5 ; J14.5 23.91,8.79 ; J14.5 21.93,6.81 ; J14.5 21.93,10.77 ; 69.12,47.11 J6.38 67.02,47.11
  vias: v1(1,98) v1(1,95) v1(1,91) v1(1,87) v1(1,83) v1(1,79) v1(1,75) v1(1,71) v1(1,67) v1(1,63) v1(1,59) v1(1,55) v1(1,51) v1(1,47) v1(1,43) v1(1,39) v1(1,35) v1(1,31) v1(1,27) v1(1,23) v1(1,19) v1(1,15) v1(1,11) v1(1,7) v1(6,17.8) v1(6.55,63.3) v1(7,104) v1(7,1) v1(8.3,17.8) v1(9,12) v1(12.85,87.7) v1(12.85,85.3) v1(14,19.5) v1(15.2,84.7) v1(15.2,82.3) v1(16,60.15) v1(16.9,103.9) v1(16.9,102) v1(17.05,61.65) v1(17.8,86.4) v1(18,32) v1(18,29.5) v1(18,27) v1(18.1,74.6) v1(18.15,57.75) v1(18.8,59.8) v1(18.8,55.75) v1(19,81.5) v1(19,7.5) v1(19,1) v1(19.5,24.5) v1(19.6,69.3) v1(21.8,98) v1(22.6,99.1) v1(23,104) v1(23,76.5) v1(23,1) v1(23.4,100.2) v1(24,18.8) v1(25,45.5) v1(25,5) v1(25.5,51) v1(25.7,14) v1(26.95,20.3) v1(27,104) v1(27,1) v1(28.5,95.85) v1(28.5,76.5) v1(29.3,20.8) v1(31,104) v1(31,92) v1(31,8.5) v1(31,1) v1(31.05,99) v1(32.5,15) v1(32.6,88.3) v1(34.9,80.85) v1(34.9,62.85) v1(35,104) v1(35,1) v1(39,104) v1(39,31) v1(39.5,51.5) v1(39.5,43) v1(39.8,11.2) v1(40,77.5) v1(42.8,99.5) v1(43,104) v1(43,18.5) v1(43,1) v1(44,11.5) v1(46,26.5) v1(47,104) v1(47,1) v1(48,15) v1(49.8,104) v1(50.5,74.5) v1(51,31.5) v1(51,23) v1(51,1) v1(51.5,12) v1(52.8,104) v1(55,104) v1(55,1) v1(55.5,17.5) v1(56.7,35.4) v1(59,104) v1(59,1) v1(59.2,13.05) v1(60.15,13.05) v1(60.5,98.5) v1(62,104) v1(63,1) v1(67,13.5) v1(67,1) v1(68,104) v1(70,104) v1(71,17.5) v1(74,104) v1(74,97) v1(75.5,101) v1(76,18.5) v1(76.5,13.5) v1(78,104) v1(78,1) v1(80,15.1) v1(84,98) v1(84,94) v1(84,90) v1(84,86) v1(84,82) v1(84,78) v1(84,74) v1(84,70) v1(84,66) v1(84,62) v1(84,58) v1(84,55) v1(84,51) v1(84,47) v1(84,43) v1(84,39) v1(84,35) v1(84,31) v1(84,27) v1(84,23) v1(84,19) v1(84,15) v1(84,11) v1(84,7)
VBUSA: length 19.9
  TOP w0.5: R19.2 40.05,4.45 C20.1
  TOP w1: J14.1 31.5,5 C19.1 C20.1
VBUSB: length 15
  TOP w0.2: 11.4,9.57 Q5.1 v1(11.4,10.65) ; 11.4,9.57 10.85,9.03 9.83,9.03 9.38,9.47 R21.1 ; 11.4,9.57 12.7,8.28 J15.1
  PWRB w0.2: v1(11.4,10.65) 12.11,10.65 J4.1
VDD_CORE: length 46.1
  TOP w0.2: v1(51.65,33.15) 56.55,33.15 62.91,26.79 J6.53 ; J1.179 24.2,33.15 v1(24.55,32.8)
  BOTTOM w0.2: v1(51.65,33.15) 50.6,32.1 34.5,32.1 33.8,32.8 v1(24.55,32.8)
CAM0_CN: length 53.3
  TOP w0.116: v1(33.56,43.56) 33.29,43.83 32.44,43.83 32.25,43.65 J1.144 ; v1(3.44,15.09) 3.86,15.09 4.13,15.36 4.89,15.36 J9.8
  BOTTOM w0.116: v1(33.56,43.56) 33.15,43.56 32.88,43.82 28.63,43.82 23.5,38.7 20.55,38.7 9.4,27.55 9.4,15.95 8.81,15.36 4.13,15.36 3.86,15.09 v1(3.44,15.09)
CAM0_CP: length 53.3
  TOP w0.116: v1(3.44,15.88) 3.86,15.88 4.13,15.61 4.86,15.61 J9.9 ; J1.142 32.25,44.25 32.44,44.07 33.29,44.07 v1(33.56,44.34)
  BOTTOM w0.116: v1(33.56,44.34) 33.15,44.34 32.88,44.08 28.53,44.08 23.4,38.95 20.45,38.95 9.15,27.65 9.15,16.05 8.71,15.61 4.13,15.61 3.86,15.88 v1(3.44,15.88)
CAM0_DN0: length 53.5
  TOP w0.116: J9.2 5.67,12.25 5.8,12.37 6.37,12.37 7.29,13.29 7.29,17.11 7.56,17.38 v1(7.56,17.8) ; v1(33.56,45.31) 33.24,45.63 32.44,45.63 32.25,45.45 J1.138
  BOTTOM w0.116: v1(7.56,17.8) 7.56,18.22 7.29,18.49 7.29,27.19 20.6,40.5 23.15,40.5 28.23,45.58 32.87,45.58 33.14,45.31 v1(33.56,45.31)
CAM0_DN1: length 53.3
  TOP w0.116: v1(33.56,41.76) 33.29,42.03 32.44,42.03 32.25,41.85 J1.150 ; v1(3.44,13.59) 3.86,13.59 4.13,13.86 4.89,13.86 J9.5
  BOTTOM w0.116: v1(33.56,41.76) 33.15,41.76 32.88,42.02 29.27,42.02 24.15,36.9 20.6,36.9 11.15,27.45 11.15,15.6 9.41,13.86 4.13,13.86 3.86,13.59 v1(3.44,13.59)
CAM0_DP0: length 53.5
  TOP w0.116: J1.136 32.25,46.05 32.44,45.87 33.33,45.87 v1(33.56,46.1) ; J9.3 5.67,12.75 5.8,12.63 6.27,12.63 7.04,13.39 7.04,17.11 6.77,17.38 v1(6.77,17.8)
  BOTTOM w0.116: v1(33.56,46.1) 33.14,46.1 32.87,45.83 28.13,45.83 23.05,40.75 20.5,40.75 7.04,27.29 7.04,18.49 6.77,18.22 v1(6.77,17.8)
CAM0_DP1: length 53.3
  TOP w0.116: J1.148 32.25,42.45 32.44,42.27 33.29,42.27 v1(33.56,42.54) ; J9.6 4.86,14.11 4.13,14.11 3.86,14.38 v1(3.44,14.38)
  BOTTOM w0.116: v1(33.56,42.54) 33.15,42.54 32.88,42.28 29.17,42.28 24.05,37.15 20.5,37.15 10.9,27.55 10.9,15.7 9.31,14.11 4.13,14.11 3.86,14.38 v1(3.44,14.38)
CAM0_IO0: length 75.7
  TOP w0.2: v1(3.7,19.2) 4.25,19.75 J9.17
  PWRB w0.2: v1(3.7,19.2) 4.8,19.2 5.4,18.6 8.8,18.6 16.9,26.7 16.9,29.6 23.8,36.5 58.36,36.5 J6.51
CAM0_IO1: length 74.8
  TOP w0.2: J9.18 v1(3.95,20.25)
  PWRB w0.2: v1(3.95,20.25) 9.05,20.25 16.35,27.55 16.35,32.75 20.63,37.03 20.91,37.03 60.37,37.03 J6.49
CAM1_CN: length 21.7
  TOP w0.116: J11.8 5.67,33.25 5.8,33.37 9.62,33.37 18.57,42.32 21.55,42.32 21.73,42.15 J1.149
CAM1_CP: length 21.7
  TOP w0.116: J11.9 5.67,33.75 5.8,33.63 9.52,33.63 18.47,42.58 21.55,42.58 21.73,42.75 J1.147
CAM1_DN0: length 21.5
  TOP w0.116: J1.161 21.73,38.55 21.55,38.72 19.73,38.72 11.38,30.37 5.8,30.37 5.67,30.25 J11.2
CAM1_DN1: length 21.6
  TOP w0.116: J1.155 21.73,40.35 21.55,40.52 19.08,40.52 10.43,31.87 5.8,31.87 5.67,31.75 J11.5
CAM1_DN2: length 21.9
  TOP w0.116: J1.143 21.73,43.95 21.55,44.12 18.03,44.12 8.78,34.87 5.8,34.87 5.67,34.75 J11.11
CAM1_DN3: length 22
  TOP w0.116: J11.14 5.67,36.25 5.8,36.37 8.28,36.37 17.83,45.92 21.55,45.92 21.73,45.75 J1.137
CAM1_DP0: length 21.5
  TOP w0.116: J1.159 21.73,39.15 21.55,38.98 19.63,38.98 11.28,30.63 5.8,30.63 5.67,30.75 J11.3
CAM1_DP1: length 21.6
  TOP w0.116: J11.6 5.67,32.25 5.8,32.13 10.33,32.13 18.98,40.78 21.55,40.78 21.73,40.95 J1.153
CAM1_DP2: length 21.9
  TOP w0.116: J11.12 5.67,35.25 5.8,35.13 8.68,35.13 17.93,44.38 21.55,44.38 21.73,44.55 J1.141
CAM1_DP3: length 22
  TOP w0.116: J1.135 21.73,46.35 21.55,46.18 17.73,46.18 8.18,36.63 5.8,36.63 5.67,36.75 J11.15
CAM1_IO0: length 62
  TOP w0.2: J11.17 v1(6.65,37.75)
  PWRB w0.2: v1(6.65,37.75) 14.25,37.75 16.85,40.35 64.67,40.35 J6.43
CAM1_IO1: length 64
  TOP w0.2: J11.18 v1(4.05,38.25)
  PWRB w0.2: J6.41 64.3,40.8 32.73,40.8 32.68,40.75 32.27,40.75 32.22,40.8 16.4,40.8 13.85,38.25 v1(4.05,38.25)
CD0_SCL: length 139
  TOP w0.2: v1(2.8,20.8) 3.25,21.25 J9.20 ; v1(2.4,73.75) 2.9,74.25 J10.20 7.27,74.25 8,74.98 R13.2
  PWRT w0.2: v1(2.4,73.75) 5.3,70.85 5.3,24.4 2.8,21.9 v1(2.8,20.8)
  PWRB w0.2: v1(2.8,20.8) 4.4,20.8 4.9,21.3 8.6,21.3 15.75,28.45 15.75,33.65 20.6,38.5 61.44,38.5 J6.47
CD0_SDA: length 138.1
  TOP w0.2: J9.21 v1(2,21.75) ; R14.2 6.24,74.75 J10.21 v1(1.95,74.75)
  PWRT w0.2: v1(1.95,74.75) 1.61,74.41 1.61,73.69 4.8,70.5 4.8,24.55 v1(2,21.75)
  PWRB w0.2: J6.45 63.38,39.1 20.3,39.1 15.15,33.95 15.15,29.75 7.15,21.75 v1(2,21.75)
CD1_SCL: length 126.1
  TOP w0.15: R16.2 6.8,93.33 5.72,92.25 J12.20
  TOP w0.2: J11.20 v1(4.15,39.25) ; J12.20 v1(4.12,92.25)
  PWRB w0.2: J6.39 62.7,47.4 23.4,47.4 22.2,46.2 20.7,46.2 13.75,39.25 v1(4.15,39.25) ; v1(6.6,42.6) 5.7,43.5 5.7,62.9 5.3,63.3 5.3,91.07 v1(4.12,92.25)
  BOTTOM w0.2: v1(6.6,42.6) 6.1,42.6 4.15,40.65 v1(4.15,39.25)
